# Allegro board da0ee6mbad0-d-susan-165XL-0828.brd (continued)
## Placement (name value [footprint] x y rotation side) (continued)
R19  100K_4  [RC0402_S]  40.15 74.19 90 top
R20  100K_4  [RC0402_S]  40.15 55.27 270 top
R21  4.7K/F_4  [RC0402_S]  40.66 63.53 270 top
R22  *100K_4  [RC0402_S]  41.04 74.19 270 top
R23  *100K_4  [RC0402_S]  41.04 55.27 90 top
R24  4.7K/F_4  [RC0402_S]  41.68 63.53 90 top
R25  *SHORT_4  [SHORT0402_S]  44.35 81.81 270 top
R26  *100K_4  [RC0402_S]  44.98 79.91 180 top
R27  *51_4  [RC0402_S]  44.98 79.02 0 top
R28  *51_4  [RC0402_S]  44.98 78.13 0 top
R29  *51_4  [RC0402_S]  44.98 77.24 0 top
R30  23.2/F_4  [RC0402_S]  45.49 65.3 180 top
R31  162/F_4  [RC0402_S]  45.49 64.42 180 top
R32  29.4/F_4  [RC0402_S]  45.49 63.53 180 top
R33  *0_4  [RC0402_S]  47.39 75.34 270 top
R34  *SHORT_4  [SHORT0402_S]  49.3 75.34 90 top
R35  *SHORT_4  [SHORT0402_S]  50.19 75.34 90 top
R36  49.9/F_4  [RC0402_S]  51.58 58.32 270 top
R37  *SHORT_4  [SHORT0402_S]  52.09 69.88 90 top
R38  51_4  [RC0402_S]  52.22 79.53 270 top
R39  49.9/F_4  [RC0402_S]  52.47 58.32 90 top
R40  51_4  [RC0402_S]  52.6 77.5 0 top
R41  *51_4  [RC0402_S]  53.11 79.53 270 top
R42  *SHORT_4  [SHORT0402_S]  53.11 69.88 90 top
R43  *SHORT_4  [SHORT0402_S]  53.36 71.53 180 top
R44  49.9/F_4  [RC0402_S]  53.36 58.32 90 top
R45  *0_2  [RC0201_S]  53.87 77.62 270 top
R46  51_4  [RC0402_S]  54 79.53 270 top
R47  *SHORT_4  [SHORT0402_S]  54.33 54.66 180 top
R48  *0_2  [RC0201_S]  54.63 77.62 270 top
R49  49.9/F_4  [RC0402_S]  54.76 58.32 90 top
R50  51_4  [RC0402_S]  54.89 79.53 270 top
R52  *0_2  [RC0201_S]  55.39 77.62 270 top
R53  *SHORT_4  [SHORT0402_S]  56.28 39.27 270 top
R54  *0_2  [RC0201_S]  56.16 77.55 270 top
R55  *0_2  [RC0201_S]  56.92 77.55 270 top
R56  *0_4  [RC0402_S]  56.92 57.68 0 top
R57  10K_4  [RC0402_S]  57.17 39.27 270 top
R58  10K_4  [RC0402_S]  54.89 35.97 0 top
R59  *SHORT_4  [SHORT0402_S]  57.55 60.86 180 top
R60  402/F_4  [RC0402_S]  57.55 59.97 180 top
R61  *0_2  [RC0201_S]  57.68 77.55 270 top
R62  47.5/F_4  [RC0402_S]  57.68 67.34 180 top
R63  150/F_4  [RC0402_S]  57.68 66.19 180 top
R64  150/F_4  [RC0402_S]  57.68 65.3 180 top
R65  47.5/F_4  [RC0402_S]  57.68 64.42 180 top
R66  4.02K/F_4  [RC0402_S]  57.68 63.53 180 top
R67  49.9/F_4  [RC0402_S]  58.06 71.02 0 top
R68  45.3/F_4  [RC0402_S]  58.06 70.13 180 top
R69  *0_2  [RC0201_S]  58.44 77.55 270 top
R70  *SHORT_4  [SHORT0402_S]  59.08 65.81 90 top
R71  *SHORT_4  [SHORT0402_S]  59.08 64.03 270 top
R72  3.3K/F_4  [RC0402_S]  60.47 41.94 270 top
R73  10K_4  [RC0402_S]  60.47 38.89 90 top
R74  10K_4  [RC0402_S]  60.47 37.11 90 top
R75  *0_2  [RC0201_S]  61.11 72.29 0 top
R76  *SHORT_4  [SHORT0402_S]  61.19 60.91 270 top
R77  *SHORT_4  [SHORT0402_S]  61.24 67.97 180 top
R78  *SHORT_4  [SHORT0402_S]  61.24 66.83 180 top
R79  3.3K_4  [RC0402_S]  61.36 41.94 90 top
R80  *10K_4  [RC0402_S]  61.49 38.89 90 top
R81  *SHORT_4  [SHORT0402_S]  62.1 64.26 90 top
R82  *SHORT_4  [SHORT0402_S]  62.1 60.91 270 top
R83  3.3K/F_4  [RC0402_S]  62.25 41.94 270 top
R84  *1K/F_4  [RC0402_S]  63.14 46.64 270 top
R85  *0_6  [RC0603]  63.4 77.57 180 top
R86  *0_2  [RC0201_S]  65.17 77.62 270 top
R87  *SHORT_4  [SHORT0402_S]  65.81 80.54 0 top
R88  *0_2  [RC0201_S]  65.94 77.62 270 top
R89  *0_2  [RC0201_S]  66.7 77.62 270 top
R90  *100K_4  [RC0402_S]  66.7 43.84 180 top
R91  *1K/F_4  [RC0402_S]  67.46 48.67 180 top
R92  0_4  [RC0402_S]  68.09 70.38 90 top
R93  1K/F_4  [RC0402_S]  68.86 76.1 180 top
R94  100K_4  [RC0402_S]  68.98 79.78 180 top
R95  0_4  [RC0402_S]  68.98 70.38 270 top
R96  0_4  [RC0402_S]  69.87 70.38 270 top
R97  0_4  [RC0402_S]  70.76 70.38 90 top
R98  680_2  [RC0201_S]  71.02 75.59 270 top
R99  *100/F_4  [RC0402]  71.14 78.77 180 top
R100  680_2  [RC0201_S]  71.78 75.59 270 top
R101  *100K_4  [RC0402_S]  71.9 55.91 180 top
R102  680_2  [RC0201_S]  72.54 75.59 270 top
R103  *100/F_4  [RC0402]  73.17 78.77 180 top
R104  680_2  [RC0201_S]  73.3 75.59 270 top
R105  680_2  [RC0201_S]  75.08 75.59 270 top
R106  *100/F_4  [RC0402]  75.21 78.77 180 top
R107  680_2  [RC0201_S]  75.84 75.59 270 top
R108  680_2  [RC0201_S]  76.6 75.59 270 top
R109  *100/F_4  [RC0402]  77.24 78.77 180 top
R110  680_2  [RC0201_S]  77.37 75.59 270 top
R111  *0_4  [RC0402_S]  78.25 60.35 270 top
R112  10K/F_4  [RC0402_S]  79.02 67.46 270 top
R113  *SHORT_4  [SHORT0402_S]  79.14 60.35 90 top
R114  *0_4  [RC0402_S]  78.03 64.8 0 top
R115  100K_4  [RC0402_S]  83.28 47.32 90 top
R116  10K/F_4  [RC0402_S]  86.71 46.08 90 top
R117  2.2K/J_4  [RC0402_S]  87.53 82.7 270 top
R118  2.2K/J_4  [RC0402_S]  87.53 80.93 270 top
R119  2.2K/J_4  [RC0402_S]  87.53 78.89 270 top
R120  2.2K/J_4  [RC0402_S]  87.53 76.86 270 top
R121  10K_4  [RC0402_S]  92.48 71.15 0 top
R122  10K_4  [RC0402_S]  92.48 70.26 0 top
R123  GS@10K_4  [RC0402_S]  92.48 69.37 0 top
R124  10K_4  [RC0402_S]  92.48 68.48 0 top
R125  10K_4  [RC0402_S]  92.48 67.59 0 top
R126  10K_4  [RC0402_S]  92.48 66.7 0 top
R127  10K_4  [RC0402_S]  92.48 65.81 0 top
R128  10K_4  [RC0402_S]  92.48 64.92 0 top
R129  10K/F_4  [RC0402_S]  92.48 46.43 90 top
R130  *10K/F_4  [RC0402_S]  93.37 46.43 270 top
R131  *SHORT_4  [SHORT0402_S]  93.95 74.86 180 top
R132  *SHORT_4  [SHORT0402_S]  93.95 73.94 180 top
R133  10K/F_4  [RC0402_S]  94.26 46.43 270 top
R134  *10K_4  [RC0402_S]  94.38 71.15 0 top
R135  *10K_4  [RC0402_S]  94.38 70.26 0 top
R136  NGS@10K_4  [RC0402_S]  94.38 69.37 0 top
R137  *10K_4  [RC0402_S]  94.38 68.48 0 top
R138  *10K_4  [RC0402_S]  94.38 67.59 0 top
R139  *10K_4  [RC0402_S]  94.38 66.7 0 top
R140  *10K_4  [RC0402_S]  94.38 65.81 0 top
R141  *10K_4  [RC0402_S]  94.38 64.92 0 top
R142  *10K/F_4  [RC0402_S]  95.15 46.43 90 top
R143  20K/F_4  [RC0402_S]  95.4 35.84 270 top
R144  *10K/F_4  [RC0402_S]  96.03 46.43 90 top
R145  10K/F_4  [RC0402_S]  96.92 46.43 270 top
R146  *10K/F_4  [RC0402_S]  97.81 46.43 270 top
R147  10K/F_4  [RC0402_S]  98.7 46.43 90 top
R148  10K_4  [RC0402_S]  100.61 76.35 180 top
R149  0_4  [RC0402_S]  98.57 75.21 0 top
R150  *0_4  [RC0402_S]  98.57 74.32 0 top
R151  100/J_4  [RC0402_S]  98.57 72.54 0 top
R152  1.62K_4  [RC0402_S]  99.34 40.41 90 top
R153  *10K/F_4  [RC0402_S]  99.56 46.43 90 top
R154  10K/F_4  [RC0402_S]  99.34 44.35 270 top
R155  10K/F_4  [RC0402_S]  100.5 46.43 270 top
R156  *10K/F_4  [RC0402_S]  100.23 44.35 90 top
R157  100K_4  [RC0402_S]  103.78 42.95 270 top
R158  *SHORT_4  [SHORT0402_S]  101.37 46.43 270 top
R159  0_4  [RC0402_S]  102 61.88 90 top
R160  100K_4  [RC0402_S]  102.26 46.43 270 top
R161  100K_4  [RC0402_S]  104.29 79.4 0 top
R162  10K_4  [RC0402_S]  108.73 69.24 90 top
R163  *SHORT_4  [SHORT0402_S]  109.62 69.24 270 top
R164  2.2_6  [RC0603]  110.26 64.03 90 top
R166  10K_4  [RC0402_S]  111.27 57.68 0 top
R167  4.7K_4  [RC0402_S]  111.27 56.8 180 top
R168  *4.7K_4  [RC0402_S]  112.16 55.4 270 top
R169  *0_4  [RC0402_S]  112.42 64.42 90 top
R170  *4.7K_4  [RC0402_S]  113.05 55.4 270 top
R171  4.7K_4  [RC0402_S]  113.94 55.4 270 top
R172  *SHORT_4  [SHORT0402_S]  114.2 64.42 270 top
R173  *SHORT_4  [SHORT0402_S]  115.08 64.42 270 top
R174  *SHORT_4  [SHORT0402_S]  116.79 69.24 270 top
R175  NG@4.7K_4  [RC0402_S]  116.86 64.42 90 top
R176  *SHORT_4  [SHORT0402_S]  117.62 55.4 270 top
R177  NG@4.7K_4  [RC0402_S]  117.75 64.42 90 top
R178  NG@10K_4  [RC0402_S]  118.51 69.24 270 top
R179  *SHORT_4  [SHORT0402_S]  120.55 63.22 180 top
R180  *SHORT_4  [SHORT0402_S]  120.55 62.26 180 top
R181  100K_4  [RC0402_S]  125.88 65.56 270 top
R182  100K_4  [RC0402_S]  126.39 59.21 90 top
R183  10K_4  [RC0402_S]  127.66 65.56 90 top
R184  *0_4  [RC0402_S]  128.67 69.11 270 top
R185  *0_4  [RC0402_S]  154.33 75.44 0 top
R186  *0_4  [RC0402_S]  154.33 76.33 0 top
R187  *SHORT_4  [SHORT0402_S]  161.19 83.06 180 top
R188  *82K/F_4  [RC0402_S]  163.6 74.42 180 top
R189  *0_4  [RC0402_S]  163.09 77.22 180 top
R190  100K_4  [RC0402_S]  154.33 79.88 0 top
R191  *100K_4  [RC0402_S]  154.33 80.77 180 top
R192  0_4  [RC0402_S]  151.79 78.61 270 top
R193  0_4  [RC0402_S]  151.66 84.48 270 top
R194  *SHORT_4  [SHORT0402_S]  2.13 46.38 90 bottom
R195  100_4  [RC0402_S]  6.88 71.91 90 bottom
R196  100_4  [RC0402_S]  7.39 65.18 270 top
R197  0_4  [RC0402_S]  5.48 68.23 0 top
R198  *SHORT_4  [SHORT0402_S]  5.48 67.34 180 top
R199  *100K/F_4  [RC0402_S]  5.48 66.45 0 top
R200  *SHORT_4  [SHORT0402_S]  12.72 46.13 180 bottom
R201  *SHORT_4  [SHORT0402_S]  12.72 45.24 0 bottom
R202  *SHORT_4  [SHORT0402_S]  13.99 43.46 0 bottom
R203  *SHORT_4  [SHORT0402_S]  13.48 52.1 90 bottom
R204  *SHORT_4  [SHORT0402_S]  14.37 52.1 270 bottom
R205  NG@0_4  [RC0402_S]  14.5 5.36 90 bottom
R206  NG@10K_4  [RC0402_S]  17.93 32.67 270 bottom
R207  0_4  [RC0402_S]  10.94 65.18 180 bottom
R208  NG@0_4  [RC0402_S]  15.01 16.16 0 bottom
R209  NG@2.2K_4  [RC0402_S]  14.5 8.15 90 bottom
R210  NG@0_4  [RC0402_S]  15.14 40.41 270 bottom
R211  NG@2.2K_4  [RC0402_S]  15.14 37.62 270 bottom
R212  *SHORT_4  [SHORT0402_S]  17.17 81.94 270 bottom
R213  0_4  [RC0402_S]  19.2 57.94 270 bottom
R214  0_4  [RC0402_S]  18.06 46.76 270 bottom
R215  10K/F_4  [RC0402_S]  18.06 44.86 270 bottom
R216  10K/F_4  [RC0402_S]  18.06 42.95 90 bottom
R217  NG@100K_4  [RC0402_S]  15.14 32.67 90 bottom
R218  NG@0_4  [RC0402_S]  20.34 37.75 0 bottom
R219  NG@100K_4  [RC0402_S]  17.42 10.31 270 bottom
R220  10K_4  [RC0402_S]  19.71 44.73 180 bottom
R221  *0_4  [RC0402_S]  19.71 43.84 0 bottom
R222  0_4  [RC0402_S]  21.87 63.15 270 bottom
R223  10K_4  [RC0402_S]  20.98 49.05 0 bottom
R224  *100K_4  [RC0402_S]  20.85 45.75 180 bottom
R225  NG@10K_4  [RC0402_S]  17.42 12.35 270 bottom
R226  *SHORT_4  [SHORT0402_S]  20.62 82.98 90 bottom
R227  100K_4  [RC0402_S]  21.49 42.32 270 bottom
R228  *SHORT_4  [SHORT0402_S]  21.99 56.67 270 bottom
R229  *0_4  [RC0402_S]  21.87 47.4 270 bottom
R230  *SHORT_4  [SHORT0402_S]  20.6 55.65 0 bottom
R231  240/F_4  [RC0402_S]  25.3 72.54 270 bottom
R232  240/F_4  [RC0402_S]  25.3 70.51 270 bottom
R233  240/F_4  [RC0402_S]  25.3 57.56 270 bottom
R234  240/F_4  [RC0402_S]  25.3 55.78 270 bottom
R235  *100K_4  [RC0402_S]  24.79 14.5 270 bottom
R236  NG@0_4  [RC0402_S]  24.79 12.47 270 bottom
R237  *0_4  [RC0402_S]  25.68 10.44 90 bottom
R238  10K/F_4  [RC0402_S]  26.18 72.54 90 bottom
R239  10K/F_4  [RC0402_S]  26.18 70.77 90 bottom
R240  10K/F_4  [RC0402_S]  26.18 58.57 270 bottom
R241  10K/F_4  [RC0402_S]  26.18 56.8 270 bottom
R242  *0_4  [RC0402_S]  26.57 10.44 90 bottom
R243  100/F_4  [RC0402_S]  26.69 79.15 0 bottom
R244  100/F_4  [RC0402_S]  26.69 78.26 0 bottom
R245  100/F_4  [RC0402_S]  26.69 77.37 0 bottom
R246  100/F_4  [RC0402_S]  26.69 76.48 0 bottom
R247  100/F_4  [RC0402_S]  26.69 52.86 0 bottom
R248  100/F_4  [RC0402_S]  26.69 51.97 0 bottom
R249  100/F_4  [RC0402_S]  26.69 51.08 0 bottom
R250  100/F_4  [RC0402_S]  26.69 50.19 0 bottom
R251  100/F_4  [RC0402_S]  26.95 80.67 270 bottom
R252  100/F_4  [RC0402_S]  27.07 48.85 90 bottom
R253  *0_4  [RC0402_S]  27.45 10.44 270 bottom
R254  100/F_4  [RC0402_S]  27.84 80.67 270 bottom
R255  100/F_4  [RC0402_S]  27.96 48.85 90 bottom
R256  GS@0_4  [RC0402_S]  28.22 24.28 270 bottom
R257  NG@4.7K/F_4  [RC0402_S]  28.34 10.44 270 bottom
R258  GS@0_4  [RC0402_S]  28.47 22.89 0 bottom
R259  GS@0_4  [RC0402_S]  28.47 22 0 bottom
R260  GS@100K_4  [RC0402_S]  28.47 21.11 180 bottom
R261  GS@0_4  [RC0402_S]  29.87 18.06 270 bottom
R262  GS@0_4  [RC0402_S]  28.47 17.55 180 bottom
R263  GS@0_4  [RC0402_S]  28.47 16.66 180 bottom
R264  100/F_4  [RC0402_S]  28.72 80.67 270 bottom
R265  100/F_4  [RC0402_S]  28.85 48.85 90 bottom
R266  GS@0_4  [RC0402_S]  29.11 24.28 270 bottom
R267  100/F_4  [RC0402_S]  30.5 80.67 270 bottom
R268  100/F_4  [RC0402_S]  30.63 48.85 90 bottom
R269  100/F_4  [RC0402_S]  31.39 80.67 270 bottom
R270  100/F_4  [RC0402_S]  31.52 48.85 90 bottom
R271  NG@0_4  [RC0402_S]  31.9 10.44 270 bottom
R272  100/F_4  [RC0402_S]  32.28 80.67 270 bottom
R273  100/F_4  [RC0402_S]  32.41 48.85 90 bottom
R274  NG@0_4  [RC0402_S]  32.79 10.44 270 bottom
R275  *SHORT_4  [SHORT0402_S]  33.3 29.74 180 bottom
R276  240/F_4  [RC0402_S]  33.17 80.67 270 bottom
R277  GS@0_4  [RC0402_S]  33.55 24.28 90 bottom
R278  NG@100K_4  [RC0402_S]  33.68 10.44 270 bottom
R279  240/F_4  [RC0402_S]  34.06 80.67 270 bottom
R280  NG@0_4  [RC0402_S]  34.57 10.44 90 bottom
R281  240/F_4  [RC0402_S]  35.07 48.92 90 bottom
R282  NG@0_4  [RC0402_S]  35.46 10.44 270 bottom
R283  240/F_4  [RC0402_S]  35.96 48.92 90 bottom
R284  NG@0_4  [RC0402_S]  36.34 10.44 270 bottom
R285  100K_4  [RC0402_S]  42.95 65.56 270 top
R286  100K_4  [RC0402_S]  42.06 65.56 270 top
R289  *4.7K_4  [RC0402_S]  48.79 48.92 270 bottom
R290  *10K_4  [RC0402_S]  49.68 48.92 270 bottom
R291  10K/J_4  [RC0402_S]  50.06 77.12 270 bottom
R292  *SHORT_4  [SHORT0402_S]  50.06 75.21 270 bottom
R293  *10K_4  [RC0402_S]  50.7 48.92 270 bottom
R294  *SHORT_4  [SHORT0402_S]  50.95 77.12 270 bottom
R295  *SHORT_4  [SHORT0402_S]  50.95 75.21 270 bottom
R296  *10K_4  [RC0402_S]  51.58 48.92 270 bottom
R297  71.5/F_4  [RC0402_S]  52.22 74.45 90 bottom
R298  10K/F_4  [RC0402_S]  53.11 78.13 90 bottom
R299  *SHORT_4  [SHORT0402_S]  53.74 51.97 180 bottom
R300  *SHORT_4  [SHORT0402_S]  53.74 51.08 180 bottom
R301  *SHORT_4  [SHORT0402_S]  53.79 53.52 0 bottom
R302  10K/F_4  [RC0402_S]  54 78.13 90 bottom
R303  *1K/F_4  [RC0402_S]  54.51 76.23 90 bottom
R304  *SHORT_4  [SHORT0402_S]  55.7 53.52 180 bottom
R305  10K/F_4  [RC0402_S]  55.78 78.13 90 bottom
R306  10K/F_4  [RC0402_S]  55.39 75.59 90 bottom
R307  10K/F_4  [RC0402_S]  56.28 75.59 90 bottom
R308  NG@0_4  [RC0402_S]  58.06 75.59 270 bottom
R309  *SHORT_4  [SHORT0402_S]  55.14 49.94 180 bottom
R310  *SHORT_4  [SHORT0402_S]  55.14 49.05 180 bottom
R311  *SHORT_4  [SHORT0402_S]  18.31 56.29 270 bottom
R312  10M_4  [RC0402_S]  60.47 75.72 0 bottom
R313  0_4  [RC0402_S]  60.86 34.95 180 bottom
R314  402/F_4  [RC0402_S]  61.36 53.24 0 bottom
R315  *SHORT_4  [SHORT0402_S]  62.25 63.83 270 bottom
R316  402/F_4  [RC0402_S]  62.56 55.78 270 bottom
R317  1K/F_4  [RC0402_S]  63.4 71.65 0 bottom
R318  1K/F_4  [RC0402_S]  63.4 70.77 0 bottom
R319  *SHORT_4  [SHORT0402_S]  63.4 68.99 180 bottom
R320  *SHORT_4  [SHORT0402_S]  63.4 68.1 0 bottom
R321  1.24K/F_4  [RC0402_S]  63.4 67.34 180 bottom
R322  1.24K/F_4  [RC0402_S]  63.4 66.45 180 bottom
R323  100K_4  [RC0402_S]  63.78 77.62 270 bottom
R324  20K/F_4  [RC0402_S]  63.78 75.85 270 bottom
R325  20K/F_4  [RC0402_S]  63.78 74.45 180 bottom
R326  1M_4  [RC0402_S]  63.27 62.59 90 bottom
R327  *SHORT_4  [SHORT0402_S]  64.03 59.59 90 bottom
R328  *200/F_4  [RC0402_S]  65.55 74.96 0 bottom
R329  150_4  [RC0402_S]  82.45 46.38 0 bottom
R330  100K_4  [RC0402_S]  86.89 77.5 270 bottom
R331  33.2K/F_4  [RC0402_S]  87.27 45.62 0 bottom
R332  10K_4  [RC0402_S]  88.29 41.81 270 bottom
R333  10K_4  [RC0402_S]  89.18 41.81 270 bottom
R334  100K_4  [RC0402_S]  91.72 48.03 90 bottom
R335  10K_4  [RC0402_S]  92.61 48.03 270 bottom
R336  10K_4  [RC0402_S]  91.97 40.54 270 bottom
R337  100K_4  [RC0402_S]  69.9 50.5 270 top
R338  200K/F_4  [RC0402_S]  92.86 40.54 90 bottom
R339  *SHORT_4  [SHORT0402_S]  93.24 38.63 270 bottom
R340  *4.7K_4  [RC0402_S]  94.38 48.03 90 bottom
R341  4.7K_4  [RC0402_S]  94.64 40.54 270 bottom
R342  *4.7K_4  [RC0402_S]  95.27 48.03 90 bottom
R343  4.7K_4  [RC0402_S]  95.53 40.54 270 bottom
R344  *SHORT_4  [SHORT0402_S]  97.3 42.19 90 bottom
R345  *10K/F_4  [RC0402_S]  96.16 48.03 90 bottom
R346  *SHORT_4  [SHORT0402_S]  99.08 42.19 270 bottom
R347  *SHORT_4  [SHORT0402_S]  99.97 42.19 270 bottom
R348  100K_4  [RC0402_S]  100.86 42.19 270 bottom
R349  *10K/F_4  [RC0402_S]  101.75 42.19 270 bottom
R350  100K_4  [RC0402_S]  103.27 40.16 270 bottom
R351  *SHORT_4  [SHORT0402_S]  110.13 68.35 90 bottom
R352  *SHORT_4  [SHORT0402_S]  110.51 66.07 0 bottom
R353  *SHORT_4  [SHORT0402_S]  111.99 80.04 0 bottom
R354  *SHORT_4  [SHORT0402_S]  113.76 80.04 0 bottom
R355  *SHORT_6  [SHORT0603]  112.54 78.89 180 bottom
R356  *SHORT_4  [SHORT0402_S]  112.67 70.54 180 bottom
R357  *SHORT_4  [SHORT0402_S]  112.68 69.72 180 bottom
R358  *SHORT_4  [SHORT0402_S]  112.67 68.76 180 bottom
R359  *4.7K_4  [RC0402_S]  113.81 60.89 90 bottom
R360  *SHORT_4  [SHORT0402_S]  111.86 65.33 90 bottom
R361  *SHORT_4  [SHORT0402_S]  112.67 71.81 270 bottom
R362  *4.7K_4  [RC0402_S]  114.7 60.89 90 bottom
R363  *SHORT_4  [SHORT0402_S]  112.82 65.33 90 bottom
R364  200K/F_4  [RC0402_S]  114.96 56.92 0 bottom
R365  *SHORT_4  [SHORT0402_S]  113.69 65.33 90 bottom
R366  4.7K_4  [RC0402_S]  116.48 60.89 90 bottom
R367  *SHORT_4  [SHORT0402_S]  115.08 77.75 180 bottom
R368  *SHORT_4  [SHORT0402_S]  114.58 65.33 90 bottom
R369  100K_4  [RC0402_S]  116.35 81.94 90 bottom
R370  4.7K_4  [RC0402_S]  117.37 60.89 90 bottom
R371  *SHORT_4  [SHORT0402_S]  115.47 65.33 90 bottom
R372  *SHORT_4  [SHORT0402_S]  116.48 77.62 270 bottom
R373  *SHORT_4  [SHORT0402_S]  118.26 60.89 90 bottom
R374  *SHORT_4  [SHORT0402_S]  116.35 65.33 90 bottom
R375  *SHORT_4  [SHORT0402_S]  118.13 81.1 90 bottom
R376  *SHORT_4  [SHORT0402_S]  117.7 79.4 270 bottom
R377  *SHORT_4  [SHORT0402_S]  117.24 65.33 90 bottom
R378  1K/F_4  [RC0402_S]  118.51 82.4 180 bottom
R379  *20/F_4  [RC0402_S]  118.13 65.36 270 bottom
R380  *20/F_4  [RC0402_S]  119.91 65.36 270 bottom
R381  *SHORT_4  [SHORT0402_S]  119.02 81.1 270 bottom
R382  *0_4  [RC0402_S]  123.34 69.24 180 top
R383  *SHORT_4  [SHORT0402_S]  124.1 79.02 270 top
R384  2.2K_4  [RC0402_S]  137.44 75.97 180 bottom
R385  1K/F_4  [RC0402_S]  138.83 76.48 90 bottom
R386  *SHORT_4  [SHORT0402_S]  168.55 74.45 90 bottom
R387  *SHORT_4  [SHORT0402_S]  165.63 74.45 90 bottom
R388  *SHORT_4  [SHORT0402_S]  139.72 76.48 270 bottom
R389  *SHORT_4  [SHORT0402_S]  166.65 74.45 90 bottom
R390  *100K_4  [RC0402_S]  161.19 81.66 0 top
R391  *SHORT_4  [SHORT0402_S]  163.98 79.63 0 top
R392  *SHORT_4  [SHORT0402_S]  163.98 80.52 0 top
R393  *SHORT_4  [SHORT0402_S]  163.98 81.41 0 top
R394  *SHORT_4  [SHORT0402_S]  163.98 82.3 0 top
R395  *SHORT_4  [SHORT0402_S]  148.61 80.27 0 bottom
R396  *SHORT_4  [SHORT0402_S]  148.61 81.15 0 bottom
R397  *SHORT_4  [SHORT0402_S]  160.17 78.49 0 top
R398  *SHORT_4  [SHORT0402_S]  150.9 80.77 180 bottom
R399  *SHORT_4  [SHORT0402_S]  150.9 79.88 180 bottom
R400  4.7K_4  [RC0402_S]  154.33 77.22 180 top
R401  *SHORT_4  [SHORT0402_S]  150.9 79 0 bottom
R402  *10K/F_4  [RC0402_S]  57.17 75.59 90 bottom
R404  200K/F_4  [RC0402_S]  112.54 51.97 270 top
R406  4.7K_4  [RC0402_S]  114.32 51.97 90 top
R407  4.7K_4  [RC0402_S]  113.43 51.97 90 top
R408  *SHORT_4  [SHORT0402_S]  120.55 58.32 0 top
R410  100K_4  [RC0402_S]  74.9 50.52 90 top
R411  *SHORT_4  [SHORT0402_S]  111.27 59.08 180 top
R663  *0_6  [RC0603]  55.01 37.75 90 top
R664  10K_4  [RC0402_S]  50.7 40.41 90 top
R667  *0_6  [RC0603]  56.79 50.83 90 bottom
R668  *0_2  [RC0201_S]  98.07 70.38 0 top
R669  *10K_4  [RC0402_S]  49.04 39.02 180 top
R670  10K_4  [RC0402_S]  95.91 63.91 180 top
R672  100K_4  [RC0402_S]  84.86 43.84 0 top
R673  *10K_4  [RC0402_S]  56.66 35.97 0 top
R674  *10K_4  [RC0402_S]  56.66 36.86 0 top
RP1  2.2KX2  [4P2R-0404]  93.88 35.97 180 top
SS1  *SHORT_2  [SHORT0201_S]  108.45 45.72 90 bottom
SS2  *SHORT_2  [SHORT0201_S]  109.55 45.72 90 bottom
SS3  *SHORT_4  [SHORT0402]  109.62 53.24 270 bottom
SW1  MTA-NC-V-T/R  [SW-MTA-NC-V-T-R-5P]  2.61 63.51 90 top
SW2  MTA-NC-V-T/R  [SW-MTA-NC-V-T-R-5P]  27.1 83.7 0 top
SW3  MTA-NC-V-T/R  [SW-MTA-NC-V-T-R-5P]  48.8 83.7 0 top
SW4  MTA-NC-V-T/R  [SW-MTA-NC-V-T-R-5P]  67.1 85.7 0 top
T1  RCLAMP0531T  [RC0402_S]  5.99 64.67 180 top
T2  RCLAMP0531T  [RC0402_S]  45.23 81.81 90 top
T3  0.2pF/5V_4  [RC0402_S]  68.98 80.67 0 top
T4  0.2pF/5V_4  [RC0402_S]  78.76 78.26 270 top
T5  0.2pF/5V_4  [RC0402_S]  79.65 78.26 270 top
T6  NG@0.8pf/5V_4  [RC0402_S]  113.18 69.24 90 top
T7  NG@0.8pf/5V_4  [RC0402_S]  114.96 69.24 90 top
T8  NG@0.8pf/5V_4  [RC0402_S]  115.85 69.24 90 top
T9  NG@0.8pf/5V_4  [RC0402_S]  117.62 69.24 90 top
T10  0.2pF/5V_4  [RC0402_S]  126.77 65.56 90 top
T11  0.2pF/5V_4  [RC0402_S]  131.47 70.51 270 top
T12  0.2pF/5V_4  [RC0402_S]  132.36 70.51 270 top
T13  0.2pF/5V_4  [RC0402_S]  133.25 70.51 270 top
T14  0.2pF/5V_4  [RC0402_S]  136.8 70.51 270 top
T15  0.2pF/5V_4  [RC0402_S]  137.69 70.51 270 top
T16  RCLAMP0531T  [RC0402_S]  14.88 81.94 90 bottom
T17  RCLAMP0531T  [RC0402_S]  16.02 81.94 90 bottom
T18  RCLAMP0531T  [RC0402_S]  21.56 82.98 270 bottom
TP1  TEST_POINT_20  [TP2050]  32.66 21.24 90 top
TP2  *PAD  [TP2050]  39.37 36.25 0 top
TP4  *PAD  [TP2050]  79.91 58.19 0 top
TP5  *PAD  [TP2050]  79.78 66.96 180 top
TP6  *PAD  [TP2050]  81.3 56.92 0 top
TP7  *PAD  [TP2050]  81.81 67.62 0 top
TP8  *PAD  [TP2050]  81.43 68.86 0 top
TP11  *PAD  [TP2050]  90.57 45.06 180 top
TP12  *PAD  [TP2050]  90.62 64.47 0 top
TP13  *PAD  [TP2050]  96.42 36.22 0 top
TP14  TEST_POINT_15  [TP2050]  113.92 43.97 180 top
TP15  TEST_POINT_15  [TP2050]  116.48 50.24 180 top
TP16  TEST_POINT_15  [TP2050]  116.48 48.92 90 top
TP17  TEST_POINT_15  [TP2050]  116.48 46.13 270 top
TP18  TEST_POINT_15  [TP2050]  117.98 44.81 180 top
TP19  TEST_POINT_15  [TP2050]  118.01 51.33 0 top
TP20  TEST_POINT_15  [TP2050]  119.28 44.88 180 top
TP21  TEST_POINT_15  [TP2050]  119.35 51.41 180 top
TP22  TEST_POINT_15  [TP2050]  119.78 50.19 180 top
TP23  TEST_POINT_15  [TP2050]  120.55 44.71 180 top
TP24  TEST_POINT_15  [TP2050]  121.28 52.76 0 top
TP25  TEST_POINT_15  [TP2050]  121.05 50.19 0 top
TP26  TEST_POINT_15  [TP2050]  120.95 45.92 180 top
TP27  *PAD  [TP2650]  125.07 59.31 0 top
TP28  TEST_POINT_15  [TP2050]  121.1 47.22 0 top
TP29  *PAD  [TP2650]  125.04 57.99 0 top
TP30  TEST_POINT_15  [TP2050]  120.29 37.39 180 top
TP31  *PAD  [TP2050]  158.14 82.17 0 top
TP32  *PAD  [TP2050]  160.3 79.94 0 top
TP33  *PAD  [TP2050]  159.79 81.94 0 top
TP34  *PAD  [TP2050]  155.62 79.38 0 top
TP35  *PAD  [TP2050]  158.67 80.42 0 top
TP36  *PAD  [TP2050]  156.99 81.41 0 top
TP37  *PAD  [TP2050]  155.6 80.65 0 top
TP38  *PAD  [TP2050]  161.44 80.77 0 top
TP39  *PAD  [TP2050]  158.77 78.61 0 top
TP40  *PAD  [TP2050]  154.58 74.68 0 top
TP41  *PAD  [TP2050]  155.98 77.47 0 top
TP42  *PAD  [TP2050]  17.42 55.78 180 bottom
TP43  *PAD  [TP2050]  33.27 11.58 180 bottom
TP44  *PAD  [TP2050]  37.06 24.26 180 bottom
TP45  *PAD  [TP2050]  46.89 79.15 180 bottom
TP46  *PAD  [TP2050]  44.45 79.81 180 bottom
TP47  *PAD  [TP2050]  48.41 79.12 180 bottom
TP48  *PAD  [TP2050]  48.84 77.88 90 bottom
TP49  *PAD  [TP2050]  47.77 76.99 180 bottom
TP50  *PAD  [TP2050]  45.77 79.81 0 bottom
TP51  *PAD  [TP2050]  49.98 78.44 180 bottom
TP52  *PAD  [TP2050]  49.78 79.71 180 bottom
TP53  *PAD  [TP2050]  46.81 77.85 180 bottom
TP54  *PAD  [TP2050]  46.48 35.08 180 bottom
TP55  *PAD  [TP2050]  46.5 33.78 180 bottom
TP56  *PAD  [TP2050]  57.68 40.72 180 bottom
TP57  *PAD  [TP2050]  59.2 52.58 180 bottom
TP58  *PAD  [TP2050]  62.46 58.07 180 bottom
TP59  *PAD  [TP2050]  75.33 61.24 0 top
TP60  *PAD  [TP2050]  75.21 59.97 0 top
TP61  *PAD  [TP2050]  76.4 59.26 0 top
TP62  *PAD  [TP2050]  125.88 76.63 180 bottom
TP63  *PAD  [TP2050]  125.88 75.13 180 bottom
TP64  *PAD  [TP2050]  108.5 50.96 180 bottom
TP65  *PAD  [TP2050]  107.72 52.01 180 bottom
TP66  *PAD  [TP2050]  107.04 50.9 180 bottom
TP67  *PAD  [TP2050]  102.38 44.48 180 bottom
TP68  *PAD  [TP2050]  14.19 54.4 180 bottom
TP69  *PAD  [TP2050]  70.26 76.63 180 bottom
U1  CM32181  [OPLGA6-2_35X1_8-6]  7.01 44.35 0 top
U2  DMIC MP45DT02TR  [MIC-MP45DT02TR-6P]  16.84 83.67 0 top
U3  *TS3A27518EZQSR  [BGA24-TEXAS-TXS02612]  48.28 78.64 270 top
U4  *LXES11DAA2-135  [FILTER-LXES11DAA2-135-6P]  62.63 71.27 180 top
U5  *FPF1320  [BGA6-FAIRCHILD-FPF1320UCX]  66.32 45.87 90 top
U7  *TS5A23159RSER(QFN)  [UQFN10-2X1_5-5-0_6H]  73.56 53.87 0 top
U8  *TS3A27518EZQSR  [BGA24-TEXAS-TXS02612]  73.68 68.23 0 top
U10  STM32F103CBU6TR  [QFN48-7X7-5-49P-STM32F103CB]  94.64 41.05 180 top
U11  PI3USB102  [TQFN10-1_6X1_3-4]  96.16 74.7 0 top
U12  NPCE948LA0BX  [BGA64-ITE-IT8562VGCX]  116.1 59.84 180 top
U13  *G5695T11U  [SOT23-2_8-95-5P-1_45H]  157.76 74.68 270 top
U14  TPS22924CYZPR  [BGA6-TEXAS-CD3271-6P]  151.41 81.81 270 top
U15  LXES11DAA2-135  [FILTER-LXES11DAA2-135-6P]  11.71 63.65 270 bottom
U16  LXES11DAA2-135  [FILTER-LXES11DAA2-135-6P]  13.1 47.91 90 bottom
U17  LXES11DAA2-135  [FILTER-LXES11DAA2-135-6P]  14.5 57.56 0 bottom
U18  LXES11DAA2-135  [FILTER-LXES11DAA2-135-6P]  15.77 47.91 90 bottom
U19  NG@STM8T143  [UFDFPN8-2X3-5-9P]  16.53 35.21 90 bottom
U20  NG@STM8T143  [UFDFPN8-2X3-5-9P]  15.39 11.46 180 bottom
U21  LXES11DAA2-135  [FILTER-LXES11DAA2-135-6P]  16.79 57.56 0 bottom
U22  GS@BCM4752IUB2G  [BGA30-BROADCOM-BCM4752IUB2G]  31.39 21.24 270 bottom
U23  SP@LPDDR3_FPGA_8  [BGA253-HYNIX-H9CCNNNBPTMLBR-NTM]  34.01 73.31 270 bottom
U24  SP@LPDDR3_FPGA_8  [BGA253-HYNIX-H9CCNNNBPTMLBR-NTM]  34.01 56.16 0 bottom
U25  GS@SAFEA1G58KA0F00R15  [FILTER-SAFEA1G57KH0F00-5P]  35.14 17.76 180 bottom
U26  SP@H26M64003DQR  [BGA169-SANDISK-SDIN5C-32G]  35.58 36.98 90 bottom
U27  GS@MAX2659ELT+  [DFN6-1_5X1-5]  38 18.37 0 bottom
U28  GS@SAFEA1G58KA0F00R15  [FILTER-SAFEA1G57KH0F00-5P]  39.9 23.78 180 bottom
U29  VLV2_EDS1P0/BGA  [BGA1380-INTEL-VALLEYVIEW-T]  51.66 64.16 180 bottom
U30  W25Q64FW  -- 8MB  [SOIC8-8-1_27]  61.87 40.62 180 bottom
U31  PCA9306  [VSSOP8-3_1-5-8P]  94.38 44.35 0 bottom
U32  L3GD20TR  [LGA16-4X4-65]  99.46 38.25 270 bottom
U33  PCA9306  [VSSOP8-3_1-5-8P]  115.97 58.7 90 bottom
U34  ALC5642-VF  [QFN48-6X6-4-49P-ALC280]  117.5 72.8 270 bottom
U35  LSM303DLHC  [LGA14-5X3-8]  170.71 80.88 270 bottom
U36  AW-AH691A  [BGA126-AZUREWAVE-AW-AH691]  158.01 77.22 270 bottom
U37  PCA9306  [VSSOP8-3_1-5-8P]  112.54 48.41 0 top
U*  -  [unnamed]  154.58 84.81 0 top
U*#2  -  [unnamed]  11.5 84.08 0 top
U*#3  -  [unnamed]  42.16 2.41 0 top
U*#4  -  [unnamed]  42.16 2.41 180 bottom
U*#5  -  [unnamed]  11.5 84.08 180 bottom
U*#6  -  [unnamed]  171.09 71.05 180 bottom
Y1  12MHz  [XTL-3_2X2_5-2_2X1_7-4P]  101.37 39.4 90 top
Y2  GS@26MHz_2ppm  [XTL-2_1X1_7-1_94X1_19]  35.58 22.89 270 bottom
Y3  32.768KHZ  [XTL-3_2X1_5-2_5-0_8H]  60.47 77.24 0 bottom
Y4  25MHz  [XTL-3_2X2_5-2_2X1_7]  65.94 62.76 90 bottom

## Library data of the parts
C1-C5 C7-C18 C25 C41 C45 C48 C55 C77-C81 C92 C94-C103 C105 C106 C108 C109 C112-C116 C118-C122 C125-C127 C129-C155 C159-C207 C209-C232 C234-C243 C252-C254 C295-C299 C301-C303 C305 C306 C310-C312 C315-C317 C319-C332 C334-C336 C338-C346 C350-C355 C357-C359 C361-C367 C369 C371-C376 C757 C758 D3 D4 D7 D8 L2 PC3-PC5 PC7-PC26 PC28-PC36 PC41-PC48 PC53 PC71 PC73 PC80 PC81 PC86 PC93 PC104 PC119-PC121 PC123-PC126 PC128 PC131-PC135 PC137 = CC0402_S
C6 C19-C24 C26-C40 C43 C44 C46 C47 C49-C54 C56-C62 C64-C68 C70 C72-C74 C82-C91 C93 C104 C107 C111 C117 C128 C244-C251 C255-C263 C265-C294 C304 C307 C313 C318 C337 C349 C368 C370 = CC0201_S
C42 C69 C71 C75 C76 C110 C123 C124 C264 C300 C308 C309 C333 C347 C348 C356 C360 PC6 PC67 PC79 PC82-PC84 PC87 PC88 PC92 PC96 PC99-PC103 PC111-PC117 PC127 PC129 PC130 = CC0603
C156-C158 PC136 = CC1206
C314 C377 C378 C437 C447 C452 C458 C466 C756 PC27 PC37-PC40 PC74 = CC0402
CN1 = AXE160224D-60P-LDH
CN2 = 51536-01001-V01-10P-L
CN3 = HDMI-46765-1301-19P
CN4 = CARD-CH1S-131-H-N-12P
CN5 CN6 = FH35C-21S-0_3SHW-21P-LDH
CN7 = MIPCI-APCI0026-P001A-75P-KB
CN8 CN14 CN15 = ANTENNA-20449-001E-4P
CN9 = FH35C-31S-0_3SHW-31P-LDH
CN10 = 50458-00801-001-8P-L
CN11 = FH34SRJ-6S-0_5SH-6P-L
CN12 = 88266-0400-4P-L
CN13 = 88511-2001-20P-L
CT1 CT2 = EMIPAD63X56
D1 D2 D5 D6 = DSM
D9 = DSMV
F1 PQ2 PQ3 PQ5 PQ13 Q7 Q8 Q22 = SOT23_213-3_3-2
HE1 = SOT23_123-2_8-1_9
HOLE1 HOLE2 = H-C71D71N
HOLE3 = O-EE6-1
HOLE4 = O-EE6-2
HOLE5 = O-EE6-3
HOLE6 = H-C236D79P2
HOLE7 = EE6-SHIELDING-7
HOLE8 = EE6-SHIELDING-8
HOLE9 = EE6-SHIELDING-11
HOLE10 = EE6-SHIELDING-10
HOLE11 = EE6-SHIELDING-6
HOLE12 = O-EE6-5
HOLE13 = H-C197D79P2
J1 = SIMCARD-159-1000302603-10P-L
L1 L5-L9 L16 L21-L24 L28-L31 PD1 PR6 PR7 PR18 PR19 PR23 PR24 PR27 PR30 PR32 PR34-PR36 PR38 PR39 PR41-PR45 PR47 PR49-PR55 PR57 PR61 PR63-PR65 PR74-PR76 PR81 PR83 PR84 PR86-PR88 PR91 PR94 PR96 PR99 PR107-PR112 PR114-PR116 PR123-PR129 PR132-PR136 PR139-PR142 PR144-PR147 PR152 PR153 R3 R4 R6 R9-R15 R18-R24 R26-R33 R36 R38-R41 R44 R46 R49 R50 R56-R58 R60 R62-R68 R72-R74 R79 R80 R83 R84 R90-R97 R101 R111 R112 R114-R130 R133-R157 R159-R162 R166-R171 R175 R177 R178 R181-R186 R188-R193 R195-R197 R199 R205-R211 R213-R225 R227 R229 R231-R274 R276-R286 R289-R291 R293 R296-R298 R302 R303 R305-R308 R312-R314 R316-R318 R321-R326 R328-R338 R340-R343 R345 R348-R350 R359 R362 R364 R366 R369 R370 R378-R380 R382 R384 R385 R390 R400 R402 R404 R406 R407 R410 R664 R669 R670 R672-R674 T1-T18 = RC0402_S
L3 PL21 PL22 PR151 R85 R164 R663 R667 = RC0603
L4 = RC0805_S
L10-L14 = CHOKE-WCM2012-4P
L15 L17-L20 L25 L26 PR2-PR4 PR8 PR14 PR16 PR17 PR20 PR22 PR25 PR26 PR28 PR29 PR31 PR33 PR37 PR58-PR60 PR66-PR71 PR77 PR80 PR85 PR89 PR92 PR93 PR95 PR100 PR117 PR118 PR122 PR137 PR138 PR148-PR150 R1 R2 R7 R8 R16 R17 R25 R34 R35 R37 R42 R43 R47 R53 R59 R70 R71 R76-R78 R81 R82 R87 R113 R131 R132 R158 R163 R172-R174 R176 R179 R180 R187 R194 R198 R200-R204 R212 R226 R228 R230 R275 R292 R294 R295 R299-R301 R304 R309-R311 R315 R319 R320 R327 R339 R344 R346 R347 R351-R354 R356-R358 R360 R361 R363 R365 R367 R368 R371-R377 R381 R383 R386-R389 R391-R399 R401 R408 R411 = SHORT0402_S
L27 = L2X1_6-1H
LED1 = LED12-22-BXY2P-C31-2C-3P
LED2 LED3 = LEDLTW-C191DS5
PAD1 PAD2 = EMIPAD98X79
PC1 PC2 PC49-PC52 PC54-PC66 PC68-PC70 PC72 PC75-PC78 PC85 PC89-PC91 PC94 PC95 PC97 PC98 PC105-PC110 PC118 = CC0805
PC122 = CC3528
PD2 PD3 = D-2_8X1_78
PD4 = D-0_9X0_6
PL1-PL5 PL7-PL18 = L2X1_6-1_6-1H
PL6 = CHOKE-1124BS-3R3M
PL19 PL20 = CHOKE-MMD-05AH-4R7M-X2Q
PQ4 PQ6 PQ10-PQ12 = PG-TSDSON-8-8P-R
PQ7-PQ9 = POWER-3_3X3_3-65-5P-SMT
PR1 = SHORT0805
PR12 PR79 PR119 PR120 PR666 R355 = SHORT0603
PR130 = RC3216
PR143 SS3 = SHORT0402
PU1 = BGA15-TEXAS-BQ27520YZFT-G3
PU2 = SOT23-5-2_8-95-5P-1_3H
PU3 = TDFN8-3X3-65-9P
PU4 = SOT23-5
PU5 = BGA224-ROHM-BD2610GW-E2-0_5S
PU6 = QFN16-3X3-5-17P-TPS61176RTE
PU7 = QFN24-4X4-5-34P
PU8 = QFN10-3X3-5-11P
Q1 Q9-Q11 Q14 Q18 Q24 = SC70-2_1-65-6P
Q2-Q6 Q12 Q13 Q15-Q17 Q23 = VMT3-1_2-8
R45 R48 R52 R54 R55 R61 R69 R75 R86 R88 R89 R98 R100 R102 R104 R105 R107 R108 R110 R668 = RC0201_S
R99 R103 R106 R109 = RC0402
RP1 = 4P2R-0404
SS1 SS2 = SHORT0201_S
SW1-SW4 = SW-MTA-NC-V-T-R-5P
TP1 TP2 TP4-TP8 TP11-TP26 TP28 TP30-TP69 = TP2050
TP27 TP29 = TP2650
U1 = OPLGA6-2_35X1_8-6
U2 = MIC-MP45DT02TR-6P
U3 U8 = BGA24-TEXAS-TXS02612
U4 U15-U18 U21 = FILTER-LXES11DAA2-135-6P
U5 = BGA6-FAIRCHILD-FPF1320UCX
U7 = UQFN10-2X1_5-5-0_6H
U10 = QFN48-7X7-5-49P-STM32F103CB
U11 = TQFN10-1_6X1_3-4
U12 = BGA64-ITE-IT8562VGCX
U13 = SOT23-2_8-95-5P-1_45H
U14 = BGA6-TEXAS-CD3271-6P
U19 U20 = UFDFPN8-2X3-5-9P
U22 = BGA30-BROADCOM-BCM4752IUB2G
U23 U24 = BGA253-HYNIX-H9CCNNNBPTMLBR-NTM
U25 U28 = FILTER-SAFEA1G57KH0F00-5P
U26 = BGA169-SANDISK-SDIN5C-32G
U27 = DFN6-1_5X1-5
U29 = BGA1380-INTEL-VALLEYVIEW-T
U30 = SOIC8-8-1_27
U31 U33 U37 = VSSOP8-3_1-5-8P
U32 = LGA16-4X4-65
U34 = QFN48-6X6-4-49P-ALC280
U35 = LGA14-5X3-8
U36 = BGA126-AZUREWAVE-AW-AH691
Y1 = XTL-3_2X2_5-2_2X1_7-4P
Y2 = XTL-2_1X1_7-1_94X1_19
Y3 = XTL-3_2X1_5-2_5-0_8H
Y4 = XTL-3_2X2_5-2_2X1_7

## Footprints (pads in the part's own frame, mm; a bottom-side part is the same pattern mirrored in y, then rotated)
4P2R-0404
  rect 0.33x0.762 smd: 1(-0.325,-0.5) 2(-0.325,0.5) 3(0.325,-0.5) 4(0.325,0.5)
50458-00801-001-8P-L
  rect 0.559x1.295 smd: 1(-7,5.025) 2(-5,5.025) 3(-3,5.025) 4(-1,5.025) 5(1,5.025) 6(3,5.025) 7(5,5.025) 8(7,5.025)
  rect 1.295x2.057 smd: 9(-10.1,0) 10(10.1,0)
51536-01001-V01-10P-L
  rect 0.305x0.66 smd: 1(-2.25,2.075) 2(-1.75,2.075) 3(-1.25,2.075) 4(-0.75,2.075) 5(-0.25,2.075) 6(0.25,2.075) 7(0.75,2.075) 8(1.25,2.075) 9(1.75,2.075) 10(2.25,2.075)
  rect 0.559x0.787 smd: 11(-3.175,0) 12(3.175,0)
88266-0400-4P-L
  rect 0.787x2.007 smd: 1(-1.875,4.05) 2(-0.625,4.05) 3(0.625,4.05) 4(1.875,4.05)
  rect 2.007x2.489 smd: 5(-4.075,0) 6(4.075,0)
88511-2001-20P-L
  rect 0.305x1.295 smd: 1(-4.75,3.3) 2(-4.25,3.3) 3(-3.75,3.3) 4(-3.25,3.3) 5(-2.75,3.3) 6(-2.25,3.3) 7(-1.75,3.3) 8(-1.25,3.3) 9(-0.75,3.3) 10(-0.25,3.3) 11(0.25,3.3) 12(0.75,3.3) 13(1.25,3.3) 14(1.75,3.3) 15(2.25,3.3) 16(2.75,3.3) 17(3.25,3.3) 18(3.75,3.3) 19(4.25,3.3) 20(4.75,3.3)
  rect 1.803x1.397 smd: 21(-6.4,0.5) 22(6.4,0.5)
ANTENNA-20449-001E-4P
  rect 0.61x0.559 smd: 1(0,-0.975)
  custom 0.145x0.145 smd: 2(0.96,0) 3(-0.96,0)
  rect 0.508x0.508 smd: 4(0,1)
AXE160224D-60P-LDH
  rect 0.203x0.508 smd: 1(-5.8,-1.05) 2(-5.4,-1.05) 3(-5,-1.05) 4(-4.6,-1.05) 5(-4.2,-1.05) 6(-3.8,-1.05) 7(-3.4,-1.05) 8(-3,-1.05) 9(-2.6,-1.05) 10(-2.2,-1.05) 11(-1.8,-1.05) 12(-1.4,-1.05) 13(-1,-1.05) 14(-0.6,-1.05) 15(-0.2,-1.05) 16(0.2,-1.05) 17(0.6,-1.05) 18(1,-1.05) 19(1.4,-1.05) 20(1.8,-1.05) 21(2.2,-1.05) 22(2.6,-1.05) 23(3,-1.05) 24(3.4,-1.05) 25(3.8,-1.05) 26(4.2,-1.05) 27(4.6,-1.05) 28(5,-1.05) 29(5.4,-1.05) 30(5.8,-1.05) 31(5.8,1.05) 32(5.4,1.05) 33(5,1.05) 34(4.6,1.05) 35(4.2,1.05) 36(3.8,1.05) 37(3.4,1.05) 38(3,1.05) 39(2.6,1.05) 40(2.2,1.05) 41(1.8,1.05) 42(1.4,1.05) 43(1,1.05) 44(0.6,1.05) 45(0.2,1.05) 46(-0.2,1.05) 47(-0.6,1.05) 48(-1,1.05) 49(-1.4,1.05) 50(-1.8,1.05) 51(-2.2,1.05) 52(-2.6,1.05) 53(-3,1.05) 54(-3.4,1.05) 55(-3.8,1.05) 56(-4.2,1.05) 57(-4.6,1.05) 58(-5,1.05) 59(-5.4,1.05) 60(-5.8,1.05)
  custom 0.195x0.195 smd: 61(-6.85,-0.91) 62(6.85,-0.91) 63(6.85,0.91) 64(-6.85,0.91)
BGA6-FAIRCHILD-FPF1320UCX
  round 0.254 smd: A1(-0.25,0.5) A2(0.25,0.5) B1(-0.25,0) B2(0.25,0) C1(-0.25,-0.5) C2(0.25,-0.5)
BGA6-TEXAS-CD3271-6P
  round 0.305 smd: A1(0.25,-0.5) A2(-0.25,-0.5) B1(0.25,0) B2(-0.25,0) C1(0.25,0.5) C2(-0.25,0.5)
BGA15-TEXAS-BQ27520YZFT-G3
  round 0.279 smd: A1(-0.5,1) A2(0,1) A3(0.5,1) B1(-0.5,0.5) B2(0,0.5) B3(0.5,0.5) C1(-0.5,0) C2(0,0) C3(0.5,0) D1(-0.5,-0.5) D2(0,-0.5) D3(0.5,-0.5) E1(-0.5,-1) E2(0,-1) E3(0.5,-1)
BGA24-TEXAS-TXS02612
  round 0.305 smd: A1(1,-1) A2(0.5,-1) A3(0,-1) A4(-0.5,-1) A5(-1,-1) B1(1,-0.5) B3(0,-0.5) B4(-0.5,-0.5) B5(-1,-0.5) C1(1,0) C2(0.5,0) C3(0,0) C4(-0.5,0) C5(-1,0) D1(1,0.5) D2(0.5,0.5) D3(0,0.5) D4(-0.5,0.5) D5(-1,0.5) E1(1,1) E2(0.5,1) E3(0,1) E4(-0.5,1) E5(-1,1)
BGA30-BROADCOM-BCM4752IUB2G
  round 0.279 smd: A1(-1,0.8) A2(-0.6,0.8) A3(-0.2,0.8) A4(0.2,0.8) A5(0.6,0.8) A6(1,0.8) B1(-1,0.4) B2(-0.6,0.4) B3(-0.2,0.4) B4(0.2,0.4) B5(0.6,0.4) B6(1,0.4) C1(-1,0) C2(-0.6,0) C3(-0.2,0) C4(0.2,0) C5(0.6,0) C6(1,0) D1(-1,-0.4) D2(-0.6,-0.4) D3(-0.2,-0.4) D4(0.2,-0.4) D5(0.6,-0.4) D6(1,-0.4) E1(-1,-0.8) E2(-0.6,-0.8) E3(-0.2,-0.8) E4(0.2,-0.8) E5(0.6,-0.8) E6(1,-0.8)
BGA64-ITE-IT8562VGCX
  round 0.254 smd: A1(-2,2) A2(-1.5,2) A3(-1,2) A4(-0.5,2) A5(0,2) A6(0.5,2) A7(1,2) A8(1.5,2) A9(2,2) B1(-2,1.5) B9(2,1.5) C1(-2,1) C9(2,1) D1(-2,0.5) D9(2,0.5) E1(-2,0) E9(2,0) F1(-2,-0.5) F9(2,-0.5) G1(-2,-1) G9(2,-1) H1(-2,-1.5) H9(2,-1.5) J1(-2,-2) J2(-1.5,-2) J3(-1,-2) J4(-0.5,-2) J5(0,-2) J6(0.5,-2) J7(1,-2) J8(1.5,-2) J9(2,-2)
  round 0.279 smd: B2(-1.5,1.5) B3(-1,1.5) B4(-0.5,1.5) B5(0,1.5) B6(0.5,1.5) B7(1,1.5) B8(1.5,1.5) C2(-1.5,1) C8(1.5,1) D2(-1.5,0.5) D4(-0.5,0.5) D5(0,0.5) D6(0.5,0.5) D8(1.5,0.5) E2(-1.5,0) E4(-0.5,0) E6(0.5,0) E8(1.5,0) F2(-1.5,-0.5) F4(-0.5,-0.5) F5(0,-0.5) F6(0.5,-0.5) F8(1.5,-0.5) G2(-1.5,-1) G8(1.5,-1) H2(-1.5,-1.5) H3(-1,-1.5) H4(-0.5,-1.5) H5(0,-1.5) H6(0.5,-1.5) H7(1,-1.5) H8(1.5,-1.5)
BGA126-AZUREWAVE-AW-AH691
  round 0.406 smd: A1(-5.4,4.05) A2(-5.4,3.15) A3(-5.4,2.25) A4(-5.4,1.35) A5(-5.4,0.45) A6(-5.4,-0.45) A7(-5.4,-1.35) A8(-5.4,-2.25) A9(-5.4,-3.15) A10(-5.4,-4.05) B1(-4.5,4.05) B2(-4.5,3.15) B3(-4.5,2.25) B4(-4.5,1.35) B5(-4.5,0.45) B6(-4.5,-0.45) B7(-4.5,-1.35) B8(-4.5,-2.25) B9(-4.5,-3.15) B10(-4.5,-4.05) C1(-3.6,4.05) C2(-3.6,3.15) C3(-3.6,2.25) C4(-3.6,1.35) C5(-3.6,0.45) C6(-3.6,-0.45) C7(-3.6,-1.35) C8(-3.6,-2.25) C9(-3.6,-3.15) C10(-3.6,-4.05) D1(-2.7,4.05) D2(-2.7,3.15) D3(-2.7,2.25) D4(-2.7,1.35) D5(-2.7,0.45) D6(-2.7,-0.45) D7(-2.7,-1.35) D8(-2.7,-2.25) D9(-2.7,-3.15) D10(-2.7,-4.05) E1(-1.8,4.05) E2(-1.8,3.15) E3(-1.8,2.25) E4(-1.8,1.35) E5(-1.8,0.45) E6(-1.8,-0.45) E7(-1.8,-1.35) E8(-1.8,-2.25) E9(-1.8,-3.15) E10(-1.8,-4.05) F1(-0.9,4.05) F2(-0.9,3.15) F3(-0.9,2.25) F4(-0.9,1.35) F5(-0.9,0.45) F6(-0.9,-0.45) F7(-0.9,-1.35) F8(-0.9,-2.25) F9(-0.9,-3.15) F10(-0.9,-4.05) G1(0,4.05) G2(0,3.15) G3(0,2.25) G4(0,1.35) G5(0,0.45) G6(0,-0.45) G7(0,-1.35) G8(0,-2.25) G9(0,-3.15) G10(0,-4.05) H1(0.9,4.05) H2(0.9,3.15) H3(0.9,2.25) H4(0.9,1.35) H5(0.9,0.45) H6(0.9,-0.45) H7(0.9,-1.35) H8(0.9,-2.25) H9(0.9,-3.15) H10(0.9,-4.05) J1(1.8,4.05) J2(1.8,3.15) J3(1.8,2.25) J4(1.8,1.35) J5(1.8,0.45) J6(1.8,-0.45) J7(1.8,-1.35) J8(1.8,-2.25) J9(1.8,-3.15) J10(1.8,-4.05) K1(2.7,4.05) K2(2.7,3.15) K3(2.7,2.25) K4(2.7,1.35) K5(2.7,0.45) K6(2.7,-0.45) K8(2.7,-2.25) K9(2.7,-3.15) K10(2.7,-4.05) L1(3.6,4.05) L2(3.6,3.15) L3(3.6,2.25) L4(3.6,1.35) L5(3.6,0.45) L6(3.6,-0.45) L8(3.6,-2.25) L9(3.6,-3.15) L10(3.6,-4.05) M1(4.5,4.05) M2(4.5,3.15) M3(4.5,2.25) M4(4.5,1.35) M5(4.5,0.45) M6(4.5,-0.45) M8(4.5,-2.25) M9(4.5,-3.15) M10(4.5,-4.05) N1(5.4,4.05) N2(5.4,3.15) N3(5.4,2.25) N4(5.4,1.35) N5(5.4,0.45) N6(5.4,-0.45) N8(5.4,-2.25) N9(5.4,-3.15) N10(5.4,-4.05)
BGA169-SANDISK-SDIN5C-32G
  round 0.279 smd: A4(-1.75,6.75) A6(-0.75,6.75) A9(0.75,6.75) A11(1.75,6.75) AA1(-3.25,-3.25) AA2(-2.75,-3.25) AA3(-2.25,-3.25) AA4(-1.75,-3.25) AA5(-1.25,-3.25) AA6(-0.75,-3.25) AA7(-0.25,-3.25) AA8(0.25,-3.25) AA9(0.75,-3.25) AA10(1.25,-3.25) AA11(1.75,-3.25) AA12(2.25,-3.25) AA13(2.75,-3.25) AA14(3.25,-3.25) AE1(-3.25,-5.25) AE14(3.25,-5.25) AG2(-2.75,-6.25) AG13(2.75,-6.25) AH4(-1.75,-6.75) AH6(-0.75,-6.75) AH9(0.75,-6.75) AH11(1.75,-6.75) B2(-2.75,6.25) B13(2.75,6.25) D1(-3.25,5.25) D14(3.25,5.25) H1(-3.25,3.25) H2(-2.75,3.25) H3(-2.25,3.25) H4(-1.75,3.25) H5(-1.25,3.25) H6(-0.75,3.25) H7(-0.25,3.25) H8(0.25,3.25) H9(0.75,3.25) H10(1.25,3.25) H11(1.75,3.25) H12(2.25,3.25) H13(2.75,3.25) H14(3.25,3.25) J1(-3.25,2.75) J2(-2.75,2.75) J3(-2.25,2.75) J4(-1.75,2.75) J5(-1.25,2.75) J6(-0.75,2.75) J7(-0.25,2.75) J8(0.25,2.75) J9(0.75,2.75) J10(1.25,2.75) J11(1.75,2.75) J12(2.25,2.75) J13(2.75,2.75) J14(3.25,2.75) K1(-3.25,2.25) K2(-2.75,2.25) K3(-2.25,2.25) K4(-1.75,2.25) K5(-1.25,2.25) K6(-0.75,2.25) K7(-0.25,2.25) K8(0.25,2.25) K9(0.75,2.25) K10(1.25,2.25) K11(1.75,2.25) K12(2.25,2.25) K13(2.75,2.25) K14(3.25,2.25) L1(-3.25,1.75) L2(-2.75,1.75) L3(-2.25,1.75) L4(-1.75,1.75) L12(2.25,1.75) L13(2.75,1.75) L14(3.25,1.75) M1(-3.25,1.25) M2(-2.75,1.25) M3(-2.25,1.25) M5(-1.25,1.25) M6(-0.75,1.25) M7(-0.25,1.25) M8(0.25,1.25) M9(0.75,1.25) M10(1.25,1.25) M12(2.25,1.25) M13(2.75,1.25) M14(3.25,1.25) N1(-3.25,0.75) N2(-2.75,0.75) N3(-2.25,0.75) N5(-1.25,0.75) N10(1.25,0.75) N12(2.25,0.75) N13(2.75,0.75) N14(3.25,0.75) P1(-3.25,0.25) P2(-2.75,0.25) P3(-2.25,0.25) P5(-1.25,0.25) P10(1.25,0.25) P12(2.25,0.25) P13(2.75,0.25) P14(3.25,0.25) R1(-3.25,-0.25) R2(-2.75,-0.25) R3(-2.25,-0.25) R5(-1.25,-0.25) R10(1.25,-0.25) R12(2.25,-0.25) R13(2.75,-0.25) R14(3.25,-0.25) T1(-3.25,-0.75) T2(-2.75,-0.75) T3(-2.25,-0.75) T5(-1.25,-0.75) T10(1.25,-0.75) T12(2.25,-0.75) T13(2.75,-0.75) T14(3.25,-0.75) U1(-3.25,-1.25) U2(-2.75,-1.25) U3(-2.25,-1.25) U5(-1.25,-1.25) U6(-0.75,-1.25) U7(-0.25,-1.25) U8(0.25,-1.25) U9(0.75,-1.25) U10(1.25,-1.25) U12(2.25,-1.25) U13(2.75,-1.25) U14(3.25,-1.25) V1(-3.25,-1.75) V2(-2.75,-1.75) V3(-2.25,-1.75) V12(2.25,-1.75) V13(2.75,-1.75) V14(3.25,-1.75) W1(-3.25,-2.25) W2(-2.75,-2.25) W3(-2.25,-2.25) W4(-1.75,-2.25) W5(-1.25,-2.25) W6(-0.75,-2.25) W7(-0.25,-2.25) W8(0.25,-2.25) W9(0.75,-2.25) W10(1.25,-2.25) W11(1.75,-2.25) W12(2.25,-2.25) W13(2.75,-2.25) W14(3.25,-2.25) Y1(-3.25,-2.75) Y2(-2.75,-2.75) Y3(-2.25,-2.75) Y4(-1.75,-2.75) Y5(-1.25,-2.75) Y6(-0.75,-2.75) Y7(-0.25,-2.75) Y8(0.25,-2.75) Y9(0.75,-2.75) Y10(1.25,-2.75) Y11(1.75,-2.75) Y12(2.25,-2.75) Y13(2.75,-2.75) Y14(3.25,-2.75)
BGA224-ROHM-BD2610GW-E2-0_5S
  round 0.254 smd: A1(-2.8,-2.8) A2(-2.8,-2.4) A3(-2.8,-2) A4(-2.8,-1.6) A5(-2.8,-1.2) A6(-2.8,-0.8) A7(-2.8,-0.4) A8(-2.8,0) A9(-2.8,0.4) A10(-2.8,0.8) A11(-2.8,1.2) A12(-2.8,1.6) A13(-2.8,2) A14(-2.8,2.4) A15(-2.8,2.8) B1(-2.4,-2.8) B2(-2.4,-2.4) B3(-2.4,-2) B4(-2.4,-1.6) B5(-2.4,-1.2) B6(-2.4,-0.8) B7(-2.4,-0.4) B8(-2.4,0) B9(-2.4,0.4) B10(-2.4,0.8) B11(-2.4,1.2) B12(-2.4,1.6) B13(-2.4,2) B14(-2.4,2.4) B15(-2.4,2.8) C1(-2,-2.8) C2(-2,-2.4) C3(-2,-2) C4(-2,-1.6) C5(-2,-1.2) C6(-2,-0.8) C7(-2,-0.4) C8(-2,0) C9(-2,0.4) C10(-2,0.8) C11(-2,1.2) C12(-2,1.6) C13(-2,2) C14(-2,2.4) C15(-2,2.8) D1(-1.6,-2.8) D2(-1.6,-2.4) D3(-1.6,-2) D4(-1.6,-1.6) D5(-1.6,-1.2) D6(-1.6,-0.8) D7(-1.6,-0.4) D8(-1.6,0) D9(-1.6,0.4) D10(-1.6,0.8) D11(-1.6,1.2) D12(-1.6,1.6) D13(-1.6,2) D14(-1.6,2.4) D15(-1.6,2.8) E1(-1.2,-2.8) E2(-1.2,-2.4) E3(-1.2,-2) E4(-1.2,-1.6) E5(-1.2,-1.2) E6(-1.2,-0.8) E7(-1.2,-0.4) E8(-1.2,0) E9(-1.2,0.4) E10(-1.2,0.8) E11(-1.2,1.2) E12(-1.2,1.6) E13(-1.2,2) E14(-1.2,2.4) E15(-1.2,2.8) F1(-0.8,-2.8) F2(-0.8,-2.4) F3(-0.8,-2) F4(-0.8,-1.6) F5(-0.8,-1.2) F6(-0.8,-0.8) F7(-0.8,-0.4) F8(-0.8,0) F9(-0.8,0.4) F10(-0.8,0.8) F11(-0.8,1.2) F12(-0.8,1.6) F13(-0.8,2) F14(-0.8,2.4) F15(-0.8,2.8) G1(-0.4,-2.8) G2(-0.4,-2.4) G3(-0.4,-2) G4(-0.4,-1.6) G5(-0.4,-1.2) G6(-0.4,-0.8) G8(-0.4,0) G9(-0.4,0.4) G10(-0.4,0.8) G11(-0.4,1.2) G12(-0.4,1.6) G13(-0.4,2) G14(-0.4,2.4) G15(-0.4,2.8) H1(0,-2.8) H2(0,-2.4) H3(0,-2) H4(0,-1.6) H5(0,-1.2) H6(0,-0.8) H7(0,-0.4) H8(0,0) H9(0,0.4) H10(0,0.8) H11(0,1.2) H12(0,1.6) H13(0,2) H14(0,2.4) H15(0,2.8) J1(0.4,-2.8) J2(0.4,-2.4) J3(0.4,-2) J4(0.4,-1.6) J5(0.4,-1.2) J6(0.4,-0.8) J7(0.4,-0.4) J8(0.4,0) J9(0.4,0.4) J10(0.4,0.8) J11(0.4,1.2) J12(0.4,1.6) J13(0.4,2) J14(0.4,2.4) J15(0.4,2.8) K1(0.8,-2.8) K2(0.8,-2.4) K3(0.8,-2) K4(0.8,-1.6) K5(0.8,-1.2) K6(0.8,-0.8) K7(0.8,-0.4) K8(0.8,0) K9(0.8,0.4) K10(0.8,0.8) K11(0.8,1.2) K12(0.8,1.6) K13(0.8,2) K14(0.8,2.4) K15(0.8,2.8) L1(1.2,-2.8) L2(1.2,-2.4) L3(1.2,-2) L4(1.2,-1.6) L5(1.2,-1.2) L6(1.2,-0.8) L7(1.2,-0.4) L8(1.2,0) L9(1.2,0.4) L10(1.2,0.8) L11(1.2,1.2) L12(1.2,1.6) L13(1.2,2) L14(1.2,2.4) L15(1.2,2.8) M1(1.6,-2.8) M2(1.6,-2.4) M3(1.6,-2) M4(1.6,-1.6) M5(1.6,-1.2) M6(1.6,-0.8) M7(1.6,-0.4) M8(1.6,0) M9(1.6,0.4) M10(1.6,0.8) M11(1.6,1.2) M12(1.6,1.6) M13(1.6,2) M14(1.6,2.4) M15(1.6,2.8) N1(2,-2.8) N2(2,-2.4) N3(2,-2) N4(2,-1.6) N5(2,-1.2) N6(2,-0.8) N7(2,-0.4) N8(2,0) N9(2,0.4) N10(2,0.8) N11(2,1.2) N12(2,1.6) N13(2,2) N14(2,2.4) N15(2,2.8) P1(2.4,-2.8) P2(2.4,-2.4) P3(2.4,-2) P4(2.4,-1.6) P5(2.4,-1.2) P6(2.4,-0.8) P7(2.4,-0.4) P8(2.4,0) P9(2.4,0.4) P10(2.4,0.8) P11(2.4,1.2) P12(2.4,1.6) P13(2.4,2) P14(2.4,2.4) P15(2.4,2.8) R1(2.8,-2.8) R2(2.8,-2.4) R3(2.8,-2) R4(2.8,-1.6) R5(2.8,-1.2) R6(2.8,-0.8) R7(2.8,-0.4) R8(2.8,0) R9(2.8,0.4) R10(2.8,0.8) R11(2.8,1.2) R12(2.8,1.6) R13(2.8,2) R14(2.8,2.4) R15(2.8,2.8)
BGA253-HYNIX-H9CCNNNBPTMLBR-NTM
  round 0.279 smd: A1(-4,4) A2(-3.5,4) A3(-3,4) A4(-2.5,4) A5(-2,4) A6(-1.5,4) A7(-1,4) A8(-0.5,4) A9(0,4) A10(0.5,4) A11(1,4) A12(1.5,4) A13(2,4) A14(2.5,4) A15(3,4) A16(3.5,4) A17(4,4) B1(-4,3.5) B2(-3.5,3.5) B3(-3,3.5) B4(-2.5,3.5) B5(-2,3.5) B6(-1.5,3.5) B7(-1,3.5) B8(-0.5,3.5) B9(0,3.5) B10(0.5,3.5) B11(1,3.5) B12(1.5,3.5) B13(2,3.5) B14(2.5,3.5) B15(3,3.5) B16(3.5,3.5) B17(4,3.5) C1(-4,3) C2(-3.5,3) C3(-3,3) C4(-2.5,3) C5(-2,3) C6(-1.5,3) C7(-1,3) C8(-0.5,3) C9(0,3) C10(0.5,3) C11(1,3) C12(1.5,3) C13(2,3) C14(2.5,3) C15(3,3) C16(3.5,3) C17(4,3) D1(-4,2.5) D2(-3.5,2.5) D3(-3,2.5) D4(-2.5,2.5) D5(-2,2.5) D6(-1.5,2.5) D7(-1,2.5) D8(-0.5,2.5) D9(0,2.5) D10(0.5,2.5) D11(1,2.5) D12(1.5,2.5) D13(2,2.5) D14(2.5,2.5) D15(3,2.5) D16(3.5,2.5) D17(4,2.5) E1(-4,2) E2(-3.5,2) E3(-3,2) E4(-2.5,2) E5(-2,2) E6(-1.5,2) E7(-1,2) E8(-0.5,2) E9(0,2) E10(0.5,2) E11(1,2) E12(1.5,2) E13(2,2) E14(2.5,2) E15(3,2) E16(3.5,2) E17(4,2) F1(-4,1.5) F2(-3.5,1.5) F3(-3,1.5) F4(-2.5,1.5) F5(-2,1.5) F12(1.5,1.5) F13(2,1.5) F14(2.5,1.5) F15(3,1.5) F16(3.5,1.5) F17(4,1.5) G1(-4,1) G2(-3.5,1) G3(-3,1) G4(-2.5,1) G5(-2,1) G12(1.5,1) G13(2,1) G14(2.5,1) G15(3,1) G16(3.5,1) G17(4,1) H1(-4,0.5) H2(-3.5,0.5) H3(-3,0.5) H4(-2.5,0.5) H5(-2,0.5) H12(1.5,0.5) H13(2,0.5) H14(2.5,0.5) H15(3,0.5) H16(3.5,0.5) H17(4,0.5) J1(-4,0) J2(-3.5,0) J3(-3,0) J4(-2.5,0) J5(-2,0) J12(1.5,0) J13(2,0) J14(2.5,0) J15(3,0) J16(3.5,0) J17(4,0) K1(-4,-0.5) K2(-3.5,-0.5) K3(-3,-0.5) K4(-2.5,-0.5) K5(-2,-0.5) K12(1.5,-0.5) K13(2,-0.5) K14(2.5,-0.5) K15(3,-0.5) K16(3.5,-0.5) K17(4,-0.5) L1(-4,-1) L2(-3.5,-1) L3(-3,-1) L4(-2.5,-1) L5(-2,-1) L12(1.5,-1) L13(2,-1) L14(2.5,-1) L15(3,-1) L16(3.5,-1) L17(4,-1) M1(-4,-1.5) M2(-3.5,-1.5) M3(-3,-1.5) M4(-2.5,-1.5) M5(-2,-1.5) M6(-1.5,-1.5) M7(-1,-1.5) M8(-0.5,-1.5) M9(0,-1.5) M10(0.5,-1.5) M11(1,-1.5) M12(1.5,-1.5) M13(2,-1.5) M14(2.5,-1.5) M15(3,-1.5) M16(3.5,-1.5) M17(4,-1.5) N1(-4,-2) N2(-3.5,-2) N3(-3,-2) N4(-2.5,-2) N5(-2,-2) N6(-1.5,-2) N7(-1,-2) N8(-0.5,-2) N9(0,-2) N10(0.5,-2) N11(1,-2) N12(1.5,-2) N13(2,-2) N14(2.5,-2) N15(3,-2) N16(3.5,-2) N17(4,-2) P1(-4,-2.5) P2(-3.5,-2.5) P3(-3,-2.5) P4(-2.5,-2.5) P5(-2,-2.5) P6(-1.5,-2.5) P7(-1,-2.5) P8(-0.5,-2.5) P9(0,-2.5) P10(0.5,-2.5) P11(1,-2.5) P12(1.5,-2.5) P13(2,-2.5) P14(2.5,-2.5) P15(3,-2.5) P16(3.5,-2.5) P17(4,-2.5) R1(-4,-3) R2(-3.5,-3) R3(-3,-3) R4(-2.5,-3) R5(-2,-3) R6(-1.5,-3) R7(-1,-3) R8(-0.5,-3) R9(0,-3) R10(0.5,-3) R11(1,-3) R12(1.5,-3) R13(2,-3) R14(2.5,-3) R15(3,-3) R16(3.5,-3) R17(4,-3) T1(-4,-3.5) T2(-3.5,-3.5) T3(-3,-3.5) T4(-2.5,-3.5) T5(-2,-3.5) T6(-1.5,-3.5) T7(-1,-3.5) T8(-0.5,-3.5) T9(0,-3.5) T10(0.5,-3.5) T11(1,-3.5) T12(1.5,-3.5) T13(2,-3.5) T14(2.5,-3.5) T15(3,-3.5) T16(3.5,-3.5) T17(4,-3.5) U1(-4,-4) U2(-3.5,-4) U3(-3,-4) U4(-2.5,-4) U5(-2,-4) U6(-1.5,-4) U7(-1,-4) U8(-0.5,-4) U9(0,-4) U10(0.5,-4) U11(1,-4) U12(1.5,-4) U13(2,-4) U14(2.5,-4) U15(3,-4) U16(3.5,-4) U17(4,-4)
BGA1380-INTEL-VALLEYVIEW-T
  round 0.25 smd: A3(-7.357,7.998) A5(-6.791,7.998) A7(-6.225,7.998) A53(6.225,7.998) A55(6.791,7.998) A57(7.357,7.998) AA3(-7.357,2.264) AA5(-6.791,2.264) AA7(-6.225,2.264) AA9(-5.659,2.264) AA11(-5.093,2.264) AA49(5.093,2.264) AA51(5.659,2.264) AA53(6.225,2.264) AA55(6.791,2.264) AA57(7.357,2.264) AB4(-7.074,1.981) AB6(-6.508,1.981) AB8(-5.942,1.981) AB10(-5.376,1.981) AB12(-4.81,1.981) AB48(4.81,1.981) AB50(5.376,1.981) AB52(5.942,1.981) AB54(6.508,1.981) AB56(7.074,1.981) AC3(-7.357,1.698) AC5(-6.791,1.698) AC7(-6.225,1.698) AC9(-5.659,1.698) AC11(-5.093,1.698) AC49(5.093,1.698) AC51(5.659,1.698) AC53(6.225,1.698) AC55(6.791,1.698) AC57(7.357,1.698) AD2(-7.715,1.415) AD4(-7.074,1.415) AD6(-6.508,1.415) AD8(-5.942,1.415) AD10(-5.376,1.415) AD12(-4.81,1.415) AD48(4.81,1.415) AD50(5.376,1.415) AD52(5.942,1.415) AD54(6.508,1.415) AD56(7.074,1.415) AD58(7.715,1.415) AE3(-7.394,1.169) AE5(-6.791,1.132) AE7(-6.225,1.132) AE9(-5.659,1.132) AE11(-5.093,1.132) AE49(5.093,1.132) AE51(5.659,1.132) AE53(6.225,1.132) AE55(6.791,1.132) AE57(7.394,1.169) AF4(-7.074,0.849) AF6(-6.508,0.849) AF8(-5.942,0.849) AF10(-5.376,0.849) AF12(-4.81,0.849) AF48(4.81,0.849) AF50(5.376,0.849) AF52(5.942,0.849) AF54(6.508,0.849) AF56(7.074,0.849) AG3(-7.394,0.529) AG5(-6.791,0.566) AG7(-6.225,0.566) AG9(-5.659,0.566) AG11(-5.093,0.566) AG49(5.093,0.566) AG51(5.659,0.566) AG53(6.225,0.566) AG55(6.791,0.566) AG57(7.394,0.529) AH2(-7.715,0.283) AH4(-7.074,0.283) AH6(-6.508,0.283) AH8(-5.942,0.283) AH10(-5.376,0.283) AH12(-4.81,0.283) AH48(4.81,0.283) AH50(5.376,0.283) AH52(5.942,0.283) AH54(6.508,0.283) AH56(7.074,0.283) AH58(7.715,0.283) AK3(-7.357,0) AK5(-6.791,0) AK7(-6.225,0) AK9(-5.659,0) AK11(-5.093,0) AK49(5.093,0) AK51(5.659,0) AK53(6.225,0) AK55(6.791,0) AK57(7.357,0) AM2(-7.715,-0.283) AM4(-7.074,-0.283) AM6(-6.508,-0.283) AM8(-5.942,-0.283) AM10(-5.376,-0.283) AM12(-4.81,-0.283) AM48(4.81,-0.283) AM50(5.376,-0.283) AM52(5.942,-0.283) AM54(6.508,-0.283) AM56(7.074,-0.283) AM58(7.715,-0.283) AN3(-7.394,-0.529) AN5(-6.791,-0.566) AN7(-6.225,-0.566) AN9(-5.659,-0.566) AN11(-5.093,-0.566) AN49(5.093,-0.566) AN51(5.659,-0.566) AN53(6.225,-0.566) AN55(6.791,-0.566) AN57(7.394,-0.529) AP4(-7.074,-0.849) AP6(-6.508,-0.849) AP8(-5.942,-0.849) AP10(-5.376,-0.849) AP12(-4.81,-0.849) AP48(4.81,-0.849) AP50(5.376,-0.849) AP52(5.942,-0.849) AP54(6.508,-0.849) AP56(7.074,-0.849) AR3(-7.394,-1.169) AR5(-6.791,-1.132) AR7(-6.225,-1.132) AR9(-5.659,-1.132) AR11(-5.093,-1.132) AR49(5.093,-1.132) AR51(5.659,-1.132) AR53(6.225,-1.132) AR55(6.791,-1.132) AR57(7.394,-1.169) AT2(-7.715,-1.415) AT4(-7.074,-1.415) AT6(-6.508,-1.415) AT8(-5.942,-1.415) AT10(-5.376,-1.415) AT12(-4.81,-1.415) AT48(4.81,-1.415) AT50(5.376,-1.415) AT52(5.942,-1.415) AT54(6.508,-1.415) AT56(7.074,-1.415) AT58(7.715,-1.415) AU3(-7.357,-1.697) AU5(-6.791,-1.697) AU7(-6.225,-1.697) AU9(-5.659,-1.697) AU11(-5.093,-1.697) AU49(5.093,-1.697) AU51(5.659,-1.697) AU53(6.225,-1.697) AU55(6.791,-1.697) AU57(7.357,-1.697) AV4(-7.074,-1.98) AV6(-6.508,-1.98) AV8(-5.942,-1.98) AV10(-5.376,-1.98) AV12(-4.81,-1.98) AV48(4.81,-1.98) AV50(5.376,-1.98) AV52(5.942,-1.98) AV54(6.508,-1.98) AV56(7.074,-1.98) AW3(-7.357,-2.263) AW5(-6.791,-2.263) AW7(-6.225,-2.263) AW9(-5.659,-2.263) AW11(-5.093,-2.263) AW49(5.093,-2.263) AW51(5.659,-2.263) AW53(6.225,-2.263) AW55(6.791,-2.263) AW57(7.357,-2.263) AY2(-7.715,-2.546) AY4(-7.074,-2.546) AY6(-6.508,-2.546) AY8(-5.942,-2.546) AY10(-5.376,-2.546) AY12(-4.81,-2.546) AY48(4.81,-2.546) AY50(5.376,-2.546) AY52(5.942,-2.546) AY54(6.508,-2.546) AY56(7.074,-2.546) AY58(7.715,-2.546) B2(-7.64,7.64) B4(-7.074,7.715) B6(-6.508,7.64) B8(-5.942,7.715) B12(-4.81,7.715) B16(-3.678,7.715) B20(-2.546,7.715) B24(-1.415,7.715) B28(-0.283,7.715) B34(0.849,7.715) B38(1.981,7.715) B42(3.113,7.715) B46(4.244,7.715) B50(5.376,7.715) B54(6.508,7.715) B56(7.074,7.64) B58(7.64,7.64) BA3(-7.394,-2.792) BA5(-6.791,-2.829) BA7(-6.225,-2.829) BA9(-5.659,-2.829) BA11(-5.093,-2.829) BA49(5.093,-2.829) BA51(5.659,-2.829) BA53(6.225,-2.829) BA55(6.791,-2.829) BA57(7.394,-2.792) BB4(-7.074,-3.112) BB6(-6.508,-3.112) BB8(-5.942,-3.112) BB10(-5.376,-3.112) BB12(-4.81,-3.112) BB48(4.81,-3.112) BB50(5.376,-3.112) BB52(5.942,-3.112) BB54(6.508,-3.112) BB56(7.074,-3.112) BC3(-7.394,-3.432) BC5(-6.791,-3.395) BC7(-6.225,-3.395) BC9(-5.659,-3.395) BC11(-5.093,-3.395) BC49(5.093,-3.395) BC51(5.659,-3.395) BC53(6.225,-3.395) BC55(6.791,-3.395) BC57(7.394,-3.432) BD2(-7.715,-3.678) BD4(-7.074,-3.678) BD6(-6.508,-3.678) BD8(-5.942,-3.678) BD10(-5.376,-3.678) BD12(-4.81,-3.678) BD48(4.81,-3.678) BD50(5.376,-3.678) BD52(5.942,-3.678) BD54(6.508,-3.678) BD56(7.074,-3.678) BD58(7.715,-3.678) BE3(-7.357,-3.961) BE5(-6.791,-3.961) BE7(-6.225,-3.961) BE9(-5.659,-3.961) BE11(-5.093,-3.961) BE49(5.093,-3.961) BE51(5.659,-3.961) BE53(6.225,-3.961) BE55(6.791,-3.961) BE57(7.357,-3.961) BF4(-7.074,-4.244) BF6(-6.508,-4.244) BF8(-5.942,-4.244) BF10(-5.376,-4.244) BF12(-4.81,-4.244) BF48(4.81,-4.244) BF50(5.376,-4.244) BF52(5.942,-4.244) BF54(6.508,-4.244) BF56(7.074,-4.244) BG3(-7.357,-4.527) BG5(-6.791,-4.527) BG7(-6.225,-4.527) BG9(-5.659,-4.527) BG11(-5.093,-4.527) BG49(5.093,-4.527) BG51(5.659,-4.527) BG53(6.225,-4.527) BG55(6.791,-4.527) BG57(7.357,-4.527) BH2(-7.715,-4.81) BH4(-7.074,-4.81) BH6(-6.508,-4.81) BH8(-5.942,-4.81) BH10(-5.376,-4.81) BH12(-4.81,-4.81) BH14(-4.244,-4.81) BH16(-3.678,-4.81) BH18(-3.112,-4.81) BH20(-2.546,-4.81) BH22(-1.98,-4.81) BH24(-1.415,-4.81) BH26(-0.849,-4.81) BH28(-0.283,-4.81) BH32(0.283,-4.81) BH34(0.849,-4.81) BH36(1.415,-4.81) BH38(1.981,-4.81) BH40(2.547,-4.81) BH42(3.113,-4.81) BH44(3.678,-4.81) BH46(4.244,-4.81) BH48(4.81,-4.81) BH50(5.376,-4.81) BH52(5.942,-4.81) BH54(6.508,-4.81) BH56(7.074,-4.81) BH58(7.715,-4.81) BJ3(-7.394,-5.056) BJ5(-6.791,-5.093) BJ7(-6.225,-5.093) BJ9(-5.659,-5.093) BJ11(-5.093,-5.093) BJ13(-4.527,-5.093) BJ15(-3.961,-5.093) BJ17(-3.395,-5.093) BJ19(-2.829,-5.093) BJ21(-2.263,-5.093) BJ23(-1.697,-5.093) BJ25(-1.132,-5.093) BJ27(-0.566,-5.093) BJ30(0,-5.093) BJ33(0.566,-5.093) BJ35(1.132,-5.093) BJ37(1.698,-5.093) BJ39(2.264,-5.093) BJ41(2.83,-5.093) BJ43(3.395,-5.093) BJ45(3.961,-5.093) BJ47(4.527,-5.093) BJ49(5.093,-5.093) BJ51(5.659,-5.093) BJ53(6.225,-5.093) BJ55(6.791,-5.093) BJ57(7.394,-5.056) BK4(-7.074,-5.376) BK6(-6.508,-5.376) BK8(-5.942,-5.376) BK10(-5.376,-5.376) BK12(-4.81,-5.376) BK14(-4.244,-5.376) BK16(-3.678,-5.376) BK18(-3.112,-5.376) BK20(-2.546,-5.376) BK22(-1.98,-5.376) BK24(-1.415,-5.376) BK26(-0.849,-5.376) BK28(-0.283,-5.376) BK32(0.283,-5.376) BK34(0.849,-5.376) BK36(1.415,-5.376) BK38(1.981,-5.376) BK40(2.547,-5.376) BK42(3.113,-5.376) BK44(3.678,-5.376) BK46(4.244,-5.376) BK48(4.81,-5.376) BK50(5.376,-5.376) BK52(5.942,-5.376) BK54(6.508,-5.376) BK56(7.074,-5.376) BL3(-7.394,-5.696) BL5(-6.791,-5.659) BL7(-6.225,-5.659) BL9(-5.659,-5.659) BL11(-5.093,-5.659) BL13(-4.527,-5.659) BL15(-3.961,-5.659) BL17(-3.395,-5.659) BL19(-2.829,-5.659) BL21(-2.263,-5.659) BL23(-1.697,-5.659) BL25(-1.132,-5.659) BL27(-0.566,-5.659) BL30(0,-5.659) BL33(0.566,-5.659) BL35(1.132,-5.659) BL37(1.698,-5.659) BL39(2.264,-5.659) BL41(2.83,-5.659) BL43(3.395,-5.659) BL45(3.961,-5.659) BL47(4.527,-5.659) BL49(5.093,-5.659) BL51(5.659,-5.659) BL53(6.225,-5.659) BL55(6.791,-5.659) BL57(7.394,-5.696) BM2(-7.715,-5.942) BM4(-7.074,-5.942) BM6(-6.508,-5.942) BM8(-5.942,-5.942) BM10(-5.376,-5.942) BM12(-4.81,-5.942) BM14(-4.244,-5.942) BM16(-3.678,-5.942) BM18(-3.112,-5.942) BM20(-2.546,-5.942) BM22(-1.98,-5.942) BM24(-1.415,-5.942) BM26(-0.849,-5.942) BM28(-0.283,-5.942) BM32(0.283,-5.942) BM34(0.849,-5.942) BM36(1.415,-5.942) BM38(1.981,-5.942) BM40(2.547,-5.942) BM42(3.113,-5.942) BM44(3.678,-5.942) BM46(4.244,-5.942) BM48(4.81,-5.942) BM50(5.376,-5.942) BM52(5.942,-5.942) BM54(6.508,-5.942) BM56(7.074,-5.942) BM58(7.715,-5.942) BN1(-7.998,-6.225) BN3(-7.357,-6.225) BN5(-6.791,-6.225) BN7(-6.225,-6.225) BN9(-5.659,-6.225) BN11(-5.093,-6.225) BN13(-4.527,-6.225) BN15(-3.961,-6.225) BN17(-3.395,-6.225) BN19(-2.829,-6.225) BN21(-2.263,-6.225) BN23(-1.697,-6.225) BN25(-1.132,-6.225) BN27(-0.566,-6.225) BN30(0,-6.225) BN33(0.566,-6.225) BN35(1.132,-6.225) BN37(1.698,-6.225) BN39(2.264,-6.225) BN41(2.83,-6.225) BN43(3.395,-6.225) BN45(3.961,-6.225) BN47(4.527,-6.225) BN49(5.093,-6.225) BN51(5.659,-6.225) BN53(6.225,-6.225) BN55(6.791,-6.225) BN57(7.357,-6.225) BN59(7.998,-6.225) BP2(-7.64,-6.508) BP4(-7.074,-6.508) BP6(-6.508,-6.508) BP8(-5.942,-6.508) BP10(-5.376,-6.508) BP12(-4.81,-6.508) BP14(-4.244,-6.508) BP16(-3.678,-6.508) BP18(-3.112,-6.508) BP20(-2.546,-6.508) BP22(-1.98,-6.508) BP24(-1.415,-6.508) BP26(-0.849,-6.508) BP28(-0.283,-6.508) BP32(0.283,-6.508) BP34(0.849,-6.508) BP36(1.415,-6.508) BP38(1.981,-6.508) BP40(2.547,-6.508) BP42(3.113,-6.508) BP44(3.678,-6.508) BP46(4.244,-6.508) BP48(4.81,-6.508) BP50(5.376,-6.508) BP52(5.942,-6.508) BP54(6.508,-6.508) BP56(7.074,-6.508) BP58(7.64,-6.508) BR1(-7.998,-6.791) BR3(-7.357,-6.791) BR5(-6.791,-6.791) BR7(-6.225,-6.791) BR9(-5.659,-6.791) BR11(-5.093,-6.791) BR13(-4.527,-6.791) BR15(-3.961,-6.791) BR17(-3.395,-6.791) BR19(-2.829,-6.791) BR21(-2.263,-6.791) BR23(-1.697,-6.791) BR25(-1.132,-6.791) BR27(-0.566,-6.791) BR30(0,-6.791) BR33(0.566,-6.791) BR35(1.132,-6.791) BR37(1.698,-6.791) BR39(2.264,-6.791) BR41(2.83,-6.791) BR43(3.395,-6.791) BR45(3.961,-6.791) BR47(4.527,-6.791) BR49(5.093,-6.791) BR51(5.659,-6.791) BR53(6.225,-6.791) BR55(6.791,-6.791) BR57(7.357,-6.791) BR59(7.998,-6.791) BT2(-7.715,-7.074) BT4(-7.074,-7.074) BT6(-6.508,-7.074) BT8(-5.942,-7.074) BT10(-5.376,-7.074) BT12(-4.81,-7.074) BT14(-4.244,-7.074) BT16(-3.678,-7.074) BT18(-3.112,-7.074) BT20(-2.546,-7.074) BT22(-1.98,-7.074) BT24(-1.415,-7.074) BT26(-0.849,-7.074) BT28(-0.283,-7.074) BT32(0.283,-7.074) BT34(0.849,-7.074) BT36(1.415,-7.074) BT38(1.981,-7.074) BT40(2.547,-7.074) BT42(3.113,-7.074) BT44(3.678,-7.074) BT46(4.244,-7.074) BT48(4.81,-7.074) BT50(5.376,-7.074) BT52(5.942,-7.074) BT54(6.508,-7.074) BT56(7.074,-7.074) BT58(7.715,-7.074) BU1(-7.998,-7.357) BU3(-7.357,-7.357) BU5(-6.791,-7.357) BU7(-6.225,-7.357) BU9(-5.696,-7.394) BU11(-5.056,-7.394) BU13(-4.527,-7.357) BU15(-3.961,-7.357) BU17(-3.432,-7.394) BU19(-2.792,-7.394) BU21(-2.263,-7.357) BU23(-1.697,-7.357) BU25(-1.169,-7.394) BU27(-0.529,-7.394) BU30(0,-7.357) BU33(0.603,-7.394) BU35(1.132,-7.357) BU37(1.698,-7.357) BU39(2.227,-7.394) BU41(2.867,-7.394) BU43(3.395,-7.357) BU45(3.961,-7.357) BU47(4.49,-7.394) BU49(5.13,-7.394) BU51(5.659,-7.357) BU53(6.225,-7.357) BU55(6.791,-7.357) BU57(7.394,-7.32) BU59(7.998,-7.357) BV2(-7.64,-7.64) BV4(-7.074,-7.715) BV6(-6.508,-7.64) BV8(-5.942,-7.715) BV12(-4.81,-7.715) BV16(-3.678,-7.715) BV20(-2.546,-7.715) BV24(-1.415,-7.715) BV28(-0.283,-7.715) BV34(0.849,-7.715) BV38(1.981,-7.715) BV42(3.113,-7.715) BV46(4.244,-7.715) BV50(5.376,-7.715) BV54(6.508,-7.715) BV56(7.074,-7.64) BV58(7.64,-7.64) BW3(-7.357,-7.998) BW5(-6.791,-7.998) BW7(-6.225,-7.998) BW53(6.225,-7.998) BW55(6.791,-7.998) BW57(7.357,-7.998) C1(-7.998,7.357) C3(-7.357,7.357) C5(-6.791,7.357) C7(-6.225,7.357) C9(-5.696,7.394) C11(-5.056,7.394) C13(-4.527,7.357) C15(-3.961,7.357) C17(-3.432,7.394) C19(-2.792,7.394) C21(-2.263,7.357) C23(-1.697,7.357) C25(-1.169,7.394) C27(-0.529,7.394) C30(0,7.357) C33(0.603,7.394) C35(1.132,7.357) C37(1.698,7.357) C39(2.227,7.394) C41(2.867,7.394) C43(3.395,7.357) C45(3.961,7.357) C47(4.49,7.394) C49(5.13,7.394) C51(5.659,7.357) C53(6.225,7.357) C55(6.791,7.357) C57(7.394,7.32) C59(7.998,7.357) D2(-7.715,7.074) D4(-7.074,7.074) D6(-6.508,7.074) D8(-5.942,7.074) D10(-5.376,7.074) D12(-4.81,7.074) D14(-4.244,7.074) D16(-3.678,7.074) D18(-3.112,7.074) D20(-2.546,7.074) D22(-1.98,7.074) D24(-1.415,7.074) D26(-0.849,7.074) D28(-0.283,7.074) D32(0.283,7.074) D34(0.849,7.074) D36(1.415,7.074) D38(1.981,7.074) D40(2.547,7.074) D42(3.113,7.074) D44(3.678,7.074) D46(4.244,7.074) D48(4.81,7.074) D50(5.376,7.074) D52(5.942,7.074) D54(6.508,7.074) D56(7.074,7.074) D58(7.715,7.074) E1(-7.998,6.791) E3(-7.357,6.791) E5(-6.791,6.791) E7(-6.225,6.791) E9(-5.659,6.791) E11(-5.093,6.791) E13(-4.527,6.791) E15(-3.961,6.791) E17(-3.395,6.791) E19(-2.829,6.791) E21(-2.263,6.791) E23(-1.697,6.791) E25(-1.132,6.791) E27(-0.566,6.791) E30(0,6.791) E33(0.566,6.791) E35(1.132,6.791) E37(1.698,6.791) E39(2.264,6.791) E41(2.83,6.791) E43(3.395,6.791) E45(3.961,6.791) E47(4.527,6.791) E49(5.093,6.791) E51(5.659,6.791) E53(6.225,6.791) E55(6.791,6.791) E57(7.357,6.791) E59(7.998,6.791) F2(-7.64,6.508) F4(-7.074,6.508) F6(-6.508,6.508) F8(-5.942,6.508) F10(-5.376,6.508) F12(-4.81,6.508) F14(-4.244,6.508) F16(-3.678,6.508) F18(-3.112,6.508) F20(-2.546,6.508) F22(-1.98,6.508) F24(-1.415,6.508) F26(-0.849,6.508) F28(-0.283,6.508) F32(0.283,6.508) F34(0.849,6.508) F36(1.415,6.508) F38(1.981,6.508) F40(2.547,6.508) F42(3.113,6.508) F44(3.678,6.508) F46(4.244,6.508) F48(4.81,6.508) F50(5.376,6.508) F52(5.942,6.508) F54(6.508,6.508) F56(7.074,6.508) F58(7.64,6.508) G1(-7.998,6.225) G3(-7.357,6.225) G5(-6.791,6.225) G7(-6.225,6.225) G9(-5.659,6.225) G11(-5.093,6.225) G13(-4.527,6.225) G15(-3.961,6.225) G17(-3.395,6.225) G19(-2.829,6.225) G21(-2.263,6.225) G23(-1.697,6.225) G25(-1.132,6.225) G27(-0.566,6.225) G30(0,6.225) G33(0.566,6.225) G35(1.132,6.225) G37(1.698,6.225) G39(2.264,6.225) G41(2.83,6.225) G43(3.395,6.225) G45(3.961,6.225) G47(4.527,6.225) G49(5.093,6.225) G51(5.659,6.225) G53(6.225,6.225) G55(6.791,6.225) G57(7.357,6.225) G59(7.998,6.225) H2(-7.715,5.942) H4(-7.074,5.942) H6(-6.508,5.942) H8(-5.942,5.942) H10(-5.376,5.942) H12(-4.81,5.942) H14(-4.244,5.942) H16(-3.678,5.942) H18(-3.112,5.942) H20(-2.546,5.942) H22(-1.98,5.942) H24(-1.415,5.942) H26(-0.849,5.942) H28(-0.283,5.942) H32(0.283,5.942) H34(0.849,5.942) H36(1.415,5.942) H38(1.981,5.942) H40(2.547,5.942) H42(3.113,5.942) H44(3.678,5.942) H46(4.244,5.942) H48(4.81,5.942) H50(5.376,5.942) H52(5.942,5.942) H54(6.508,5.942) H56(7.074,5.942) H58(7.715,5.942) J3(-7.394,5.696) J5(-6.791,5.659) J7(-6.225,5.659) J9(-5.659,5.659) J11(-5.093,5.659) J13(-4.527,5.659) J15(-3.961,5.659) J17(-3.395,5.659) J19(-2.829,5.659) J21(-2.263,5.659) J23(-1.697,5.659) J25(-1.132,5.659) J27(-0.566,5.659) J30(0,5.659) J33(0.566,5.659) J35(1.132,5.659) J37(1.698,5.659) J39(2.264,5.659) J41(2.83,5.659) J43(3.395,5.659) J45(3.961,5.659) J47(4.527,5.659) J49(5.093,5.659) J51(5.659,5.659) J53(6.225,5.659) J55(6.791,5.659) J57(7.394,5.696) K4(-7.074,5.376) K6(-6.508,5.376) K8(-5.942,5.376) K10(-5.376,5.376) K12(-4.81,5.376) K14(-4.244,5.376) K16(-3.678,5.376) K18(-3.112,5.376) K20(-2.546,5.376) K22(-1.98,5.376) K24(-1.415,5.376) K26(-0.849,5.376) K28(-0.283,5.376) K32(0.283,5.376) K34(0.849,5.376) K36(1.415,5.376) K38(1.981,5.376) K40(2.547,5.376) K42(3.113,5.376) K44(3.678,5.376) K46(4.244,5.376) K48(4.81,5.376) K50(5.376,5.376) K52(5.942,5.376) K54(6.508,5.376) K56(7.074,5.376) L3(-7.394,5.056) L5(-6.791,5.093) L7(-6.225,5.093) L9(-5.659,5.093) L11(-5.093,5.093) L13(-4.527,5.093) L15(-3.961,5.093) L17(-3.395,5.093) L19(-2.829,5.093) L21(-2.263,5.093) L23(-1.697,5.093) L25(-1.132,5.093) L27(-0.566,5.093) L30(0,5.093) L33(0.566,5.093) L35(1.132,5.093) L37(1.698,5.093) L39(2.264,5.093) L41(2.83,5.093) L43(3.395,5.093) L45(3.961,5.093) L47(4.527,5.093) L49(5.093,5.093) L51(5.659,5.093) L53(6.225,5.093) L55(6.791,5.093) L57(7.394,5.056) M2(-7.715,4.81) M4(-7.074,4.81) M6(-6.508,4.81) M8(-5.942,4.81) M10(-5.376,4.81) M12(-4.81,4.81) M14(-4.244,4.81) M16(-3.678,4.81) M18(-3.112,4.81) M20(-2.546,4.81) M22(-1.98,4.81) M24(-1.415,4.81) M26(-0.849,4.81) M28(-0.283,4.81) M32(0.283,4.81) M34(0.849,4.81) M36(1.415,4.81) M38(1.981,4.81) M40(2.547,4.81) M42(3.113,4.81) M44(3.678,4.81) M46(4.244,4.81) M48(4.81,4.81) M50(5.376,4.81) M52(5.942,4.81) M54(6.508,4.81) M56(7.074,4.81) M58(7.715,4.81) N3(-7.357,4.527) N5(-6.791,4.527) N7(-6.225,4.527) N9(-5.659,4.527) N11(-5.093,4.527) N49(5.093,4.527) N51(5.659,4.527) N53(6.225,4.527) N55(6.791,4.527) N57(7.357,4.527) P4(-7.074,4.244) P6(-6.508,4.244) P8(-5.942,4.244) P10(-5.376,4.244) P12(-4.81,4.244) P48(4.81,4.244) P50(5.376,4.244) P52(5.942,4.244) P54(6.508,4.244) P56(7.074,4.244) R3(-7.357,3.961) R5(-6.791,3.961) R7(-6.225,3.961) R9(-5.659,3.961) R11(-5.093,3.961) R49(5.093,3.961) R51(5.659,3.961) R53(6.225,3.961) R55(6.791,3.961) R57(7.357,3.961) T2(-7.715,3.678) T4(-7.074,3.678) T6(-6.508,3.678) T8(-5.942,3.678) T10(-5.376,3.678) T12(-4.81,3.678) T48(4.81,3.678) T50(5.376,3.678) T52(5.942,3.678) T54(6.508,3.678) T56(7.074,3.678) T58(7.715,3.678) U3(-7.394,3.433) U5(-6.791,3.395) U7(-6.225,3.395) U9(-5.659,3.395) U11(-5.093,3.395) U49(5.093,3.395) U51(5.659,3.395) U53(6.225,3.395) U55(6.791,3.395) U57(7.394,3.433) V4(-7.074,3.113) V6(-6.508,3.113) V8(-5.942,3.113) V10(-5.376,3.113) V12(-4.81,3.113) V48(4.81,3.113) V50(5.376,3.113) V52(5.942,3.113) V54(6.508,3.113) V56(7.074,3.113) W3(-7.394,2.792) W5(-6.791,2.83) W7(-6.225,2.83) W9(-5.659,2.83) W11(-5.093,2.83) W49(5.093,2.83) W51(5.659,2.83) W53(6.225,2.83) W55(6.791,2.83) W57(7.394,2.792) Y2(-7.715,2.547) Y4(-7.074,2.547) Y6(-6.508,2.547) Y8(-5.942,2.547) Y10(-5.376,2.547) Y12(-4.81,2.547) Y48(4.81,2.547) Y50(5.376,2.547) Y52(5.942,2.547) Y54(6.508,2.547) Y56(7.074,2.547) Y58(7.715,2.547)
  round 0.325 smd: A9(-5.659,7.998) A11(-5.093,7.998) A13(-4.527,7.998) A15(-3.961,7.998) A17(-3.395,7.998) A19(-2.829,7.998) A21(-2.263,7.998) A23(-1.697,7.998) A25(-1.132,7.998) A27(-0.566,7.998) A30(0,7.998) A33(0.566,7.998) A35(1.132,7.998) A37(1.698,7.998) A39(2.264,7.998) A41(2.83,7.998) A43(3.395,7.998) A45(3.961,7.998) A47(4.527,7.998) A49(5.093,7.998) A51(5.659,7.998) AA1(-7.998,2.264) AA59(7.998,2.264) AB2(-7.64,1.981) AB58(7.64,1.981) AC1(-7.998,1.698) AC59(7.998,1.698) AE1(-7.998,1.132) AE59(7.998,1.132) AF2(-7.64,0.849) AF58(7.64,0.849) AG1(-7.998,0.566) AG59(7.998,0.566) AK1(-7.998,0) AK59(7.998,0) AN1(-7.998,-0.566) AN59(7.998,-0.566) AP2(-7.64,-0.849) AP58(7.64,-0.849) AR1(-7.998,-1.132) AR59(7.998,-1.132) AU1(-7.998,-1.697) AU59(7.998,-1.697) AV2(-7.64,-1.98) AV58(7.64,-1.98) AW1(-7.998,-2.263) AW59(7.998,-2.263) B10(-5.376,7.64) B14(-4.244,7.64) B18(-3.112,7.64) B22(-1.98,7.64) B26(-0.849,7.64) B32(0.283,7.64) B36(1.415,7.64) B40(2.547,7.64) B44(3.678,7.64) B48(4.81,7.64) B52(5.942,7.64) BA1(-7.998,-2.829) BA59(7.998,-2.829) BB2(-7.64,-3.112) BB58(7.64,-3.112) BC1(-7.998,-3.395) BC59(7.998,-3.395) BE1(-7.998,-3.961) BE59(7.998,-3.961) BF2(-7.64,-4.244) BF58(7.64,-4.244) BG1(-7.998,-4.527) BG59(7.998,-4.527) BJ1(-7.998,-5.093) BJ59(7.998,-5.093) BK2(-7.64,-5.376) BK58(7.64,-5.376) BL1(-7.998,-5.659) BL59(7.998,-5.659) BV10(-5.376,-7.64) BV14(-4.244,-7.64) BV18(-3.112,-7.64) BV22(-1.98,-7.64) BV26(-0.849,-7.64) BV32(0.283,-7.64) BV36(1.415,-7.64) BV40(2.547,-7.64) BV44(3.678,-7.64) BV48(4.81,-7.64) BV52(5.942,-7.64) BW9(-5.659,-7.998) BW11(-5.093,-7.998) BW13(-4.527,-7.998) BW15(-3.961,-7.998) BW17(-3.395,-7.998) BW19(-2.829,-7.998) BW21(-2.263,-7.998) BW23(-1.697,-7.998) BW25(-1.132,-7.998) BW27(-0.566,-7.998) BW30(0,-7.998) BW33(0.566,-7.998) BW35(1.132,-7.998) BW37(1.698,-7.998) BW39(2.264,-7.998) BW41(2.83,-7.998) BW43(3.395,-7.998) BW45(3.961,-7.998) BW47(4.527,-7.998) BW49(5.093,-7.998) BW51(5.659,-7.998) J1(-7.998,5.659) J59(7.998,5.659) K2(-7.64,5.376) K58(7.64,5.376) L1(-7.998,5.093) L59(7.998,5.093) N1(-7.998,4.527) N59(7.998,4.527) P2(-7.64,4.244) P58(7.64,4.244) R1(-7.998,3.961) R59(7.998,3.961) U1(-7.998,3.395) U59(7.998,3.395) V2(-7.64,3.113) V58(7.64,3.113) W1(-7.998,2.83) W59(7.998,2.83)
  round 0.279 smd: AA15(-3.989,2.383) AA17(-3.439,2.383) AA19(-2.888,2.383) AA21(-2.338,2.383) AA23(-1.788,2.383) AA25(-1.238,2.383) AA27(-0.688,2.383) AA29(-0.137,2.383) AA32(0.413,2.383) AA34(0.963,2.383) AA36(1.513,2.383) AA38(2.063,2.383) AA40(2.614,2.383) AA42(3.164,2.383) AA44(3.714,2.383) AA46(4.264,2.383) AC14(-4.264,1.906) AC16(-3.714,1.906) AC18(-3.164,1.906) AC20(-2.613,1.906) AC22(-2.063,1.906) AC24(-1.513,1.906) AC26(-0.963,1.906) AC28(-0.412,1.906) AC31(0.138,1.906) AC33(0.688,1.906) AC35(1.238,1.906) AC37(1.788,1.906) AC39(2.339,1.906) AC41(2.889,1.906) AC43(3.439,1.906) AC45(3.989,1.906) AD15(-3.989,1.43) AD17(-3.439,1.43) AD19(-2.888,1.43) AD21(-2.338,1.43) AD23(-1.788,1.43) AD25(-1.238,1.43) AD27(-0.688,1.43) AD29(-0.137,1.43) AD32(0.413,1.43) AD34(0.963,1.43) AD36(1.513,1.43) AD38(2.063,1.43) AD40(2.614,1.43) AD42(3.164,1.43) AD44(3.714,1.43) AD46(4.264,1.43) AF14(-4.264,0.953) AF16(-3.714,0.953) AF18(-3.164,0.953) AF20(-2.613,0.953) AF22(-2.063,0.953) AF24(-1.513,0.953) AF26(-0.963,0.953) AF28(-0.412,0.953) AF31(0.138,0.953) AF33(0.688,0.953) AF35(1.238,0.953) AF37(1.788,0.953) AF39(2.339,0.953) AF41(2.889,0.953) AF43(3.439,0.953) AF45(3.989,0.953) AH15(-3.989,0.477) AH17(-3.439,0.477) AH19(-2.888,0.477) AH21(-2.338,0.477) AH23(-1.788,0.477) AH25(-1.238,0.477) AH27(-0.688,0.477) AH29(-0.137,0.477) AH32(0.413,0.477) AH34(0.963,0.477) AH36(1.513,0.477) AH38(2.063,0.477) AH40(2.614,0.477) AH42(3.164,0.477) AH44(3.714,0.477) AH46(4.264,0.477) AK14(-4.264,0) AK16(-3.714,0) AK18(-3.164,0) AK20(-2.613,0) AK22(-2.063,0) AK24(-1.513,0) AK26(-0.963,0) AK28(-0.412,0) AK31(0.138,0) AK33(0.688,0) AK35(1.238,0) AK37(1.788,0) AK39(2.339,0) AK41(2.889,0) AK43(3.439,0) AK45(3.989,0) AM15(-3.989,-0.477) AM17(-3.439,-0.477) AM19(-2.888,-0.477) AM21(-2.338,-0.477) AM23(-1.788,-0.477) AM25(-1.238,-0.477) AM27(-0.688,-0.477) AM29(-0.137,-0.477) AM32(0.413,-0.477) AM34(0.963,-0.477) AM36(1.513,-0.477) AM38(2.063,-0.477) AM40(2.614,-0.477) AM42(3.164,-0.477) AM44(3.714,-0.477) AM46(4.264,-0.477) AP14(-4.264,-0.953) AP16(-3.714,-0.953) AP18(-3.164,-0.953) AP20(-2.613,-0.953) AP22(-2.063,-0.953) AP24(-1.513,-0.953) AP26(-0.963,-0.953) AP28(-0.412,-0.953) AP31(0.138,-0.953) AP33(0.688,-0.953) AP35(1.238,-0.953) AP37(1.788,-0.953) AP39(2.339,-0.953) AP41(2.889,-0.953) AP43(3.439,-0.953) AP45(3.989,-0.953) AT15(-3.989,-1.43) AT17(-3.439,-1.43) AT19(-2.888,-1.43) AT21(-2.338,-1.43) AT23(-1.788,-1.43) AT25(-1.238,-1.43) AT27(-0.688,-1.43) AT29(-0.137,-1.43) AT32(0.413,-1.43) AT34(0.963,-1.43) AT36(1.513,-1.43) AT38(2.063,-1.43) AT40(2.614,-1.43) AT42(3.164,-1.43) AT44(3.714,-1.43) AT46(4.264,-1.43) AU14(-4.264,-1.906) AU16(-3.714,-1.906) AU18(-3.164,-1.906) AU20(-2.613,-1.906) AU22(-2.063,-1.906) AU24(-1.513,-1.906) AU26(-0.963,-1.906) AU28(-0.412,-1.906) AU31(0.138,-1.906) AU33(0.688,-1.906) AU35(1.238,-1.906) AU37(1.788,-1.906) AU39(2.339,-1.906) AU41(2.889,-1.906) AU43(3.439,-1.906) AU45(3.989,-1.906) AW15(-3.989,-2.383) AW17(-3.439,-2.383) AW19(-2.888,-2.383) AW21(-2.338,-2.383) AW23(-1.788,-2.383) AW25(-1.238,-2.383) AW27(-0.688,-2.383) AW29(-0.137,-2.383) AW32(0.413,-2.383) AW34(0.963,-2.383) AW36(1.513,-2.383) AW38(2.063,-2.383) AW40(2.614,-2.383) AW42(3.164,-2.383) AW44(3.714,-2.383) AW46(4.264,-2.383) BA14(-4.264,-2.859) BA16(-3.714,-2.859) BA18(-3.164,-2.859) BA20(-2.613,-2.859) BA22(-2.063,-2.859) BA24(-1.513,-2.859) BA26(-0.963,-2.859) BA28(-0.412,-2.859) BA31(0.138,-2.859) BA33(0.688,-2.859) BA35(1.238,-2.859) BA37(1.788,-2.859) BA39(2.339,-2.859) BA41(2.889,-2.859) BA43(3.439,-2.859) BA45(3.989,-2.859) BB15(-3.989,-3.336) BB17(-3.439,-3.336) BB19(-2.888,-3.336) BB21(-2.338,-3.336) BB23(-1.788,-3.336) BB25(-1.238,-3.336) BB27(-0.688,-3.336) BB29(-0.137,-3.336) BB32(0.413,-3.336) BB34(0.963,-3.336) BB36(1.513,-3.336) BB38(2.063,-3.336) BB40(2.614,-3.336) BB42(3.164,-3.336) BB44(3.714,-3.336) BB46(4.264,-3.336) BD14(-4.264,-3.812) BD16(-3.714,-3.812) BD18(-3.164,-3.812) BD20(-2.613,-3.812) BD22(-2.063,-3.812) BD24(-1.513,-3.812) BD26(-0.963,-3.812) BD28(-0.412,-3.812) BD31(0.138,-3.812) BD33(0.688,-3.812) BD35(1.238,-3.812) BD37(1.788,-3.812) BD39(2.339,-3.812) BD41(2.889,-3.812) BD43(3.439,-3.812) BD45(3.989,-3.812) BF15(-3.989,-4.289) BF17(-3.439,-4.289) BF19(-2.888,-4.289) BF21(-2.338,-4.289) BF23(-1.788,-4.289) BF25(-1.238,-4.289) BF27(-0.688,-4.289) BF29(-0.137,-4.289) BF32(0.413,-4.289) BF34(0.963,-4.289) BF36(1.513,-4.289) BF38(2.063,-4.289) BF40(2.614,-4.289) BF42(3.164,-4.289) BF44(3.714,-4.289) BF46(4.264,-4.289) P15(-3.989,4.289) P17(-3.439,4.289) P19(-2.888,4.289) P21(-2.338,4.289) P23(-1.788,4.289) P25(-1.238,4.289) P27(-0.688,4.289) P29(-0.137,4.289) P32(0.413,4.289) P34(0.963,4.289) P36(1.513,4.289) P38(2.063,4.289) P40(2.614,4.289) P42(3.164,4.289) P44(3.714,4.289) P46(4.264,4.289) T14(-4.264,3.812) T16(-3.714,3.812) T18(-3.164,3.812) T20(-2.613,3.812) T22(-2.063,3.812) T24(-1.513,3.812) T26(-0.963,3.812) T28(-0.412,3.812) T31(0.138,3.812) T33(0.688,3.812) T35(1.238,3.812) T37(1.788,3.812) T39(2.339,3.812) T41(2.889,3.812) T43(3.439,3.812) T45(3.989,3.812) V15(-3.989,3.336) V17(-3.439,3.336) V19(-2.888,3.336) V21(-2.338,3.336) V23(-1.788,3.336) V25(-1.238,3.336) V27(-0.688,3.336) V29(-0.137,3.336) V32(0.413,3.336) V34(0.963,3.336) V36(1.513,3.336) V38(2.063,3.336) V40(2.614,3.336) V42(3.164,3.336) V44(3.714,3.336) V46(4.264,3.336) W14(-4.264,2.859) W16(-3.714,2.859) W18(-3.164,2.859) W20(-2.613,2.859) W22(-2.063,2.859) W24(-1.513,2.859) W26(-0.963,2.859) W28(-0.412,2.859) W31(0.138,2.859) W33(0.688,2.859) W35(1.238,2.859) W37(1.788,2.859) W39(2.339,2.859) W41(2.889,2.859) W43(3.439,2.859) W45(3.989,2.859)
